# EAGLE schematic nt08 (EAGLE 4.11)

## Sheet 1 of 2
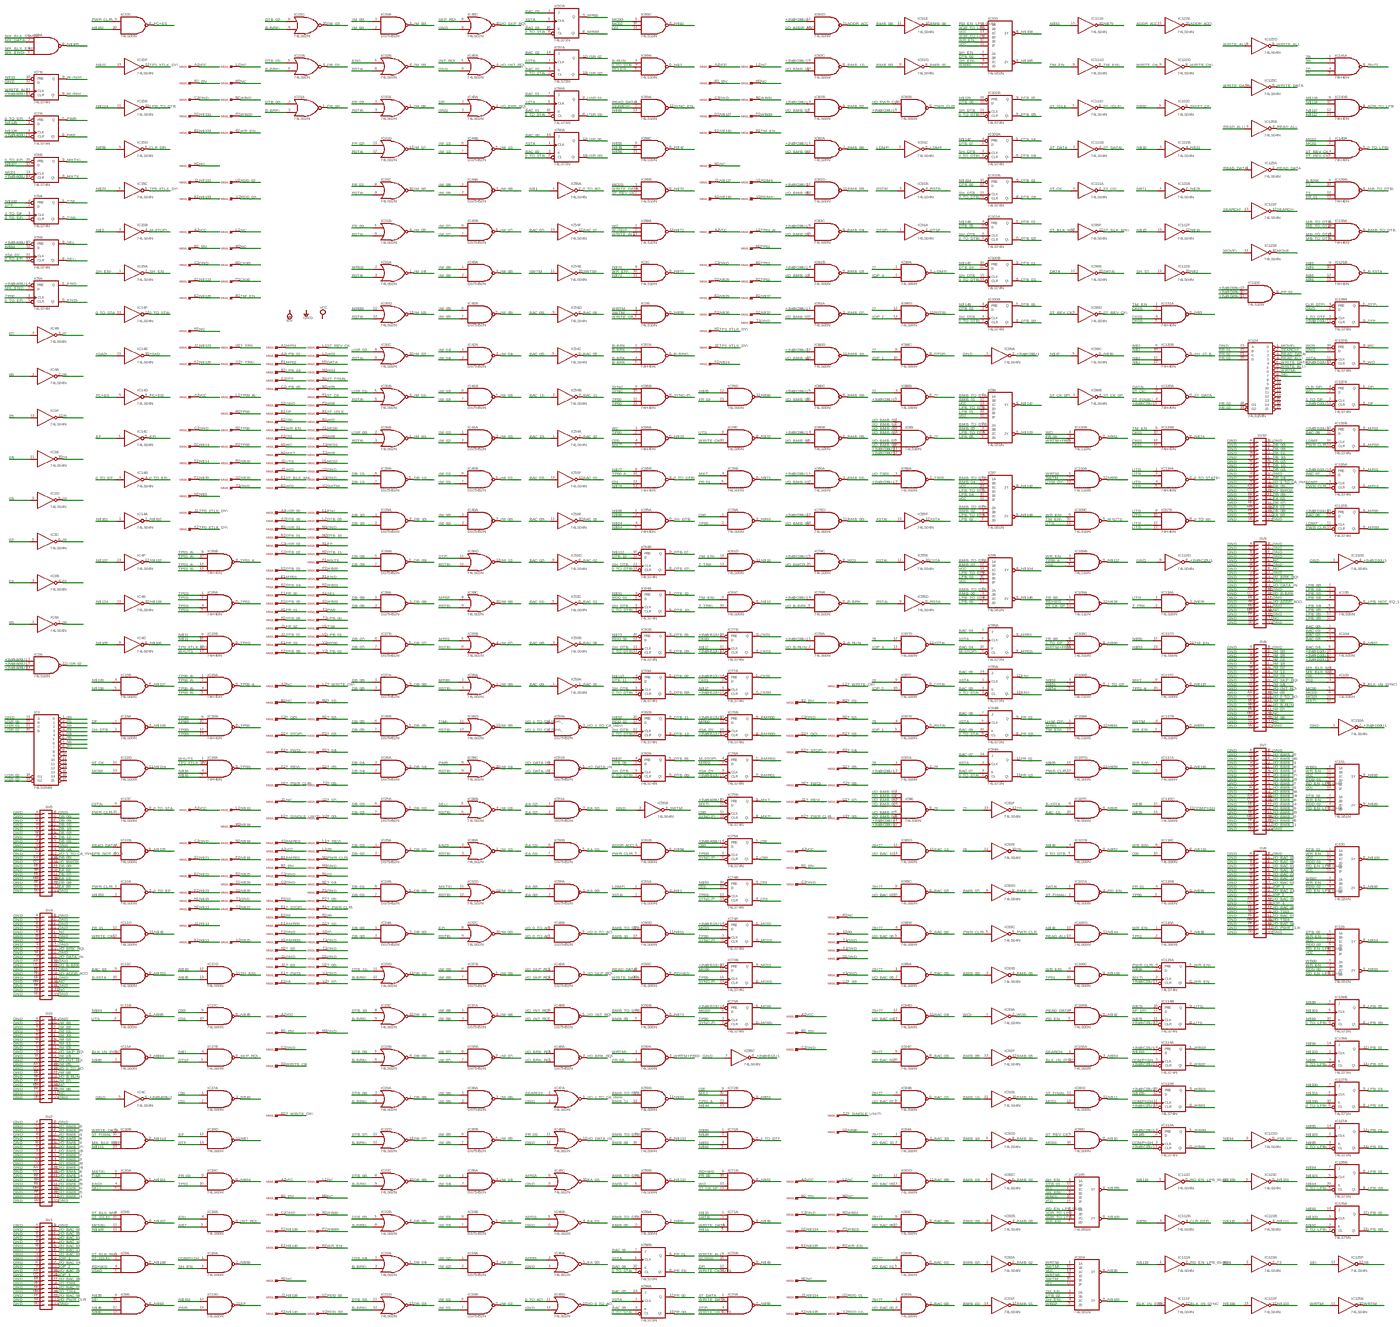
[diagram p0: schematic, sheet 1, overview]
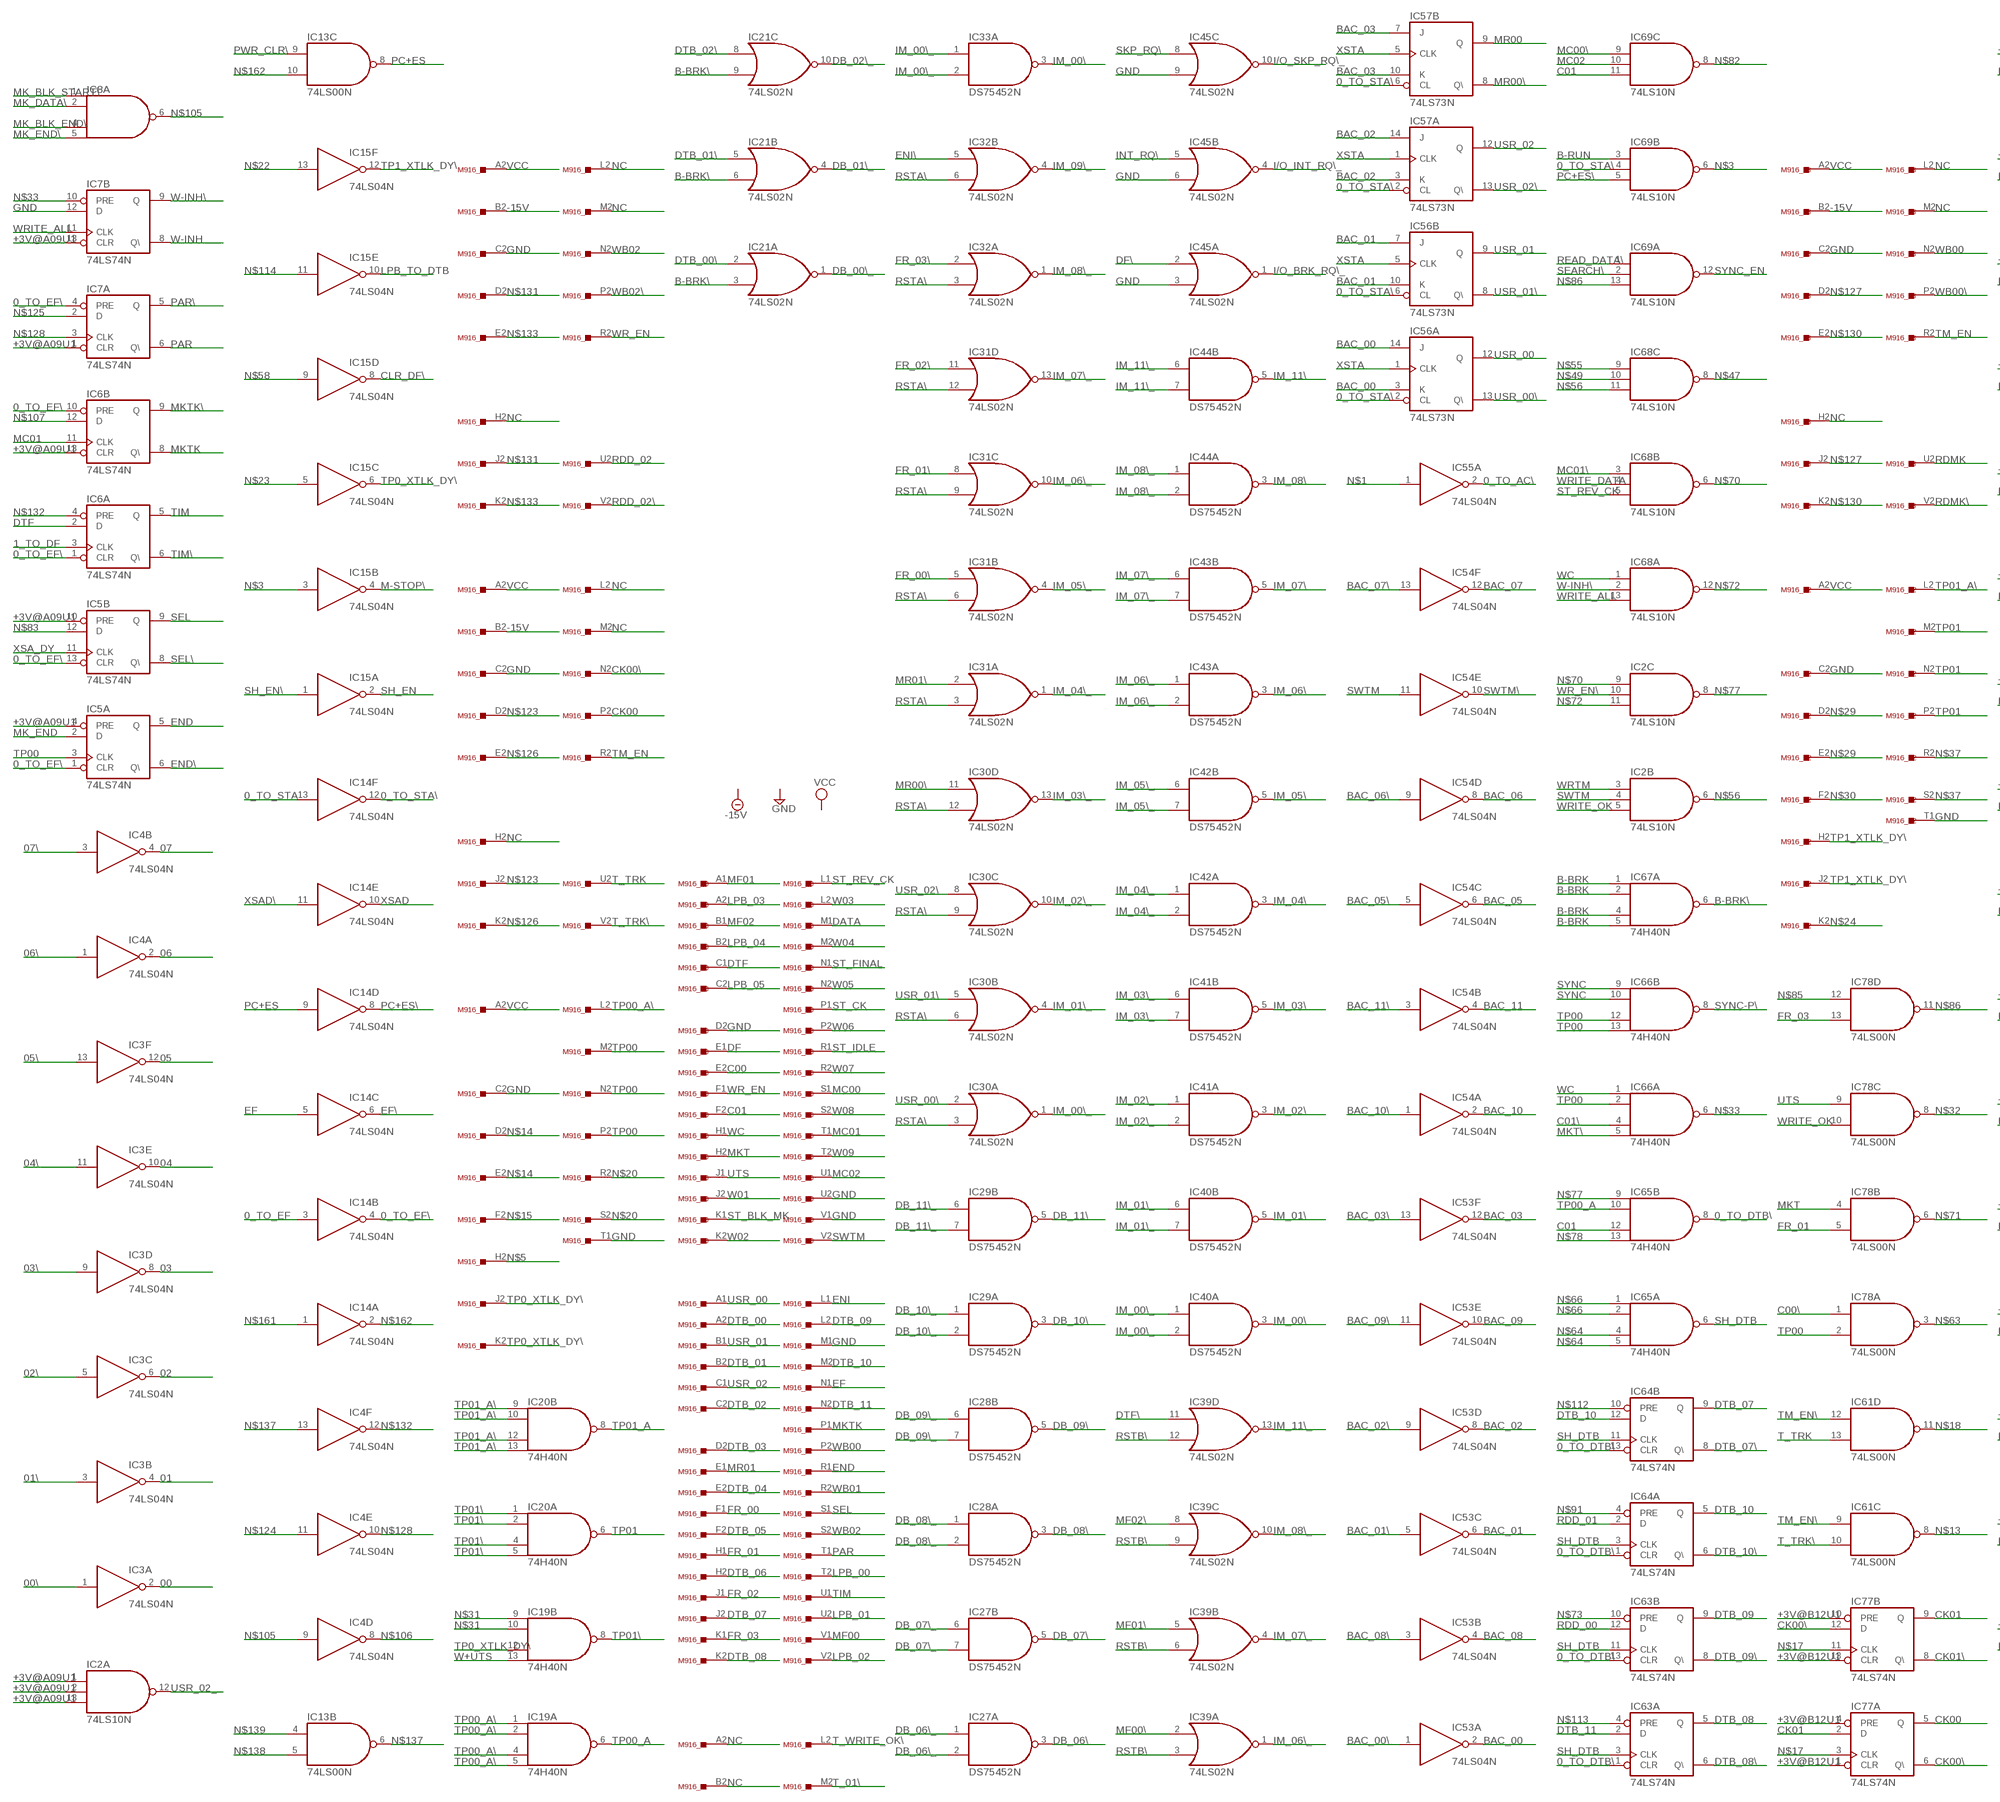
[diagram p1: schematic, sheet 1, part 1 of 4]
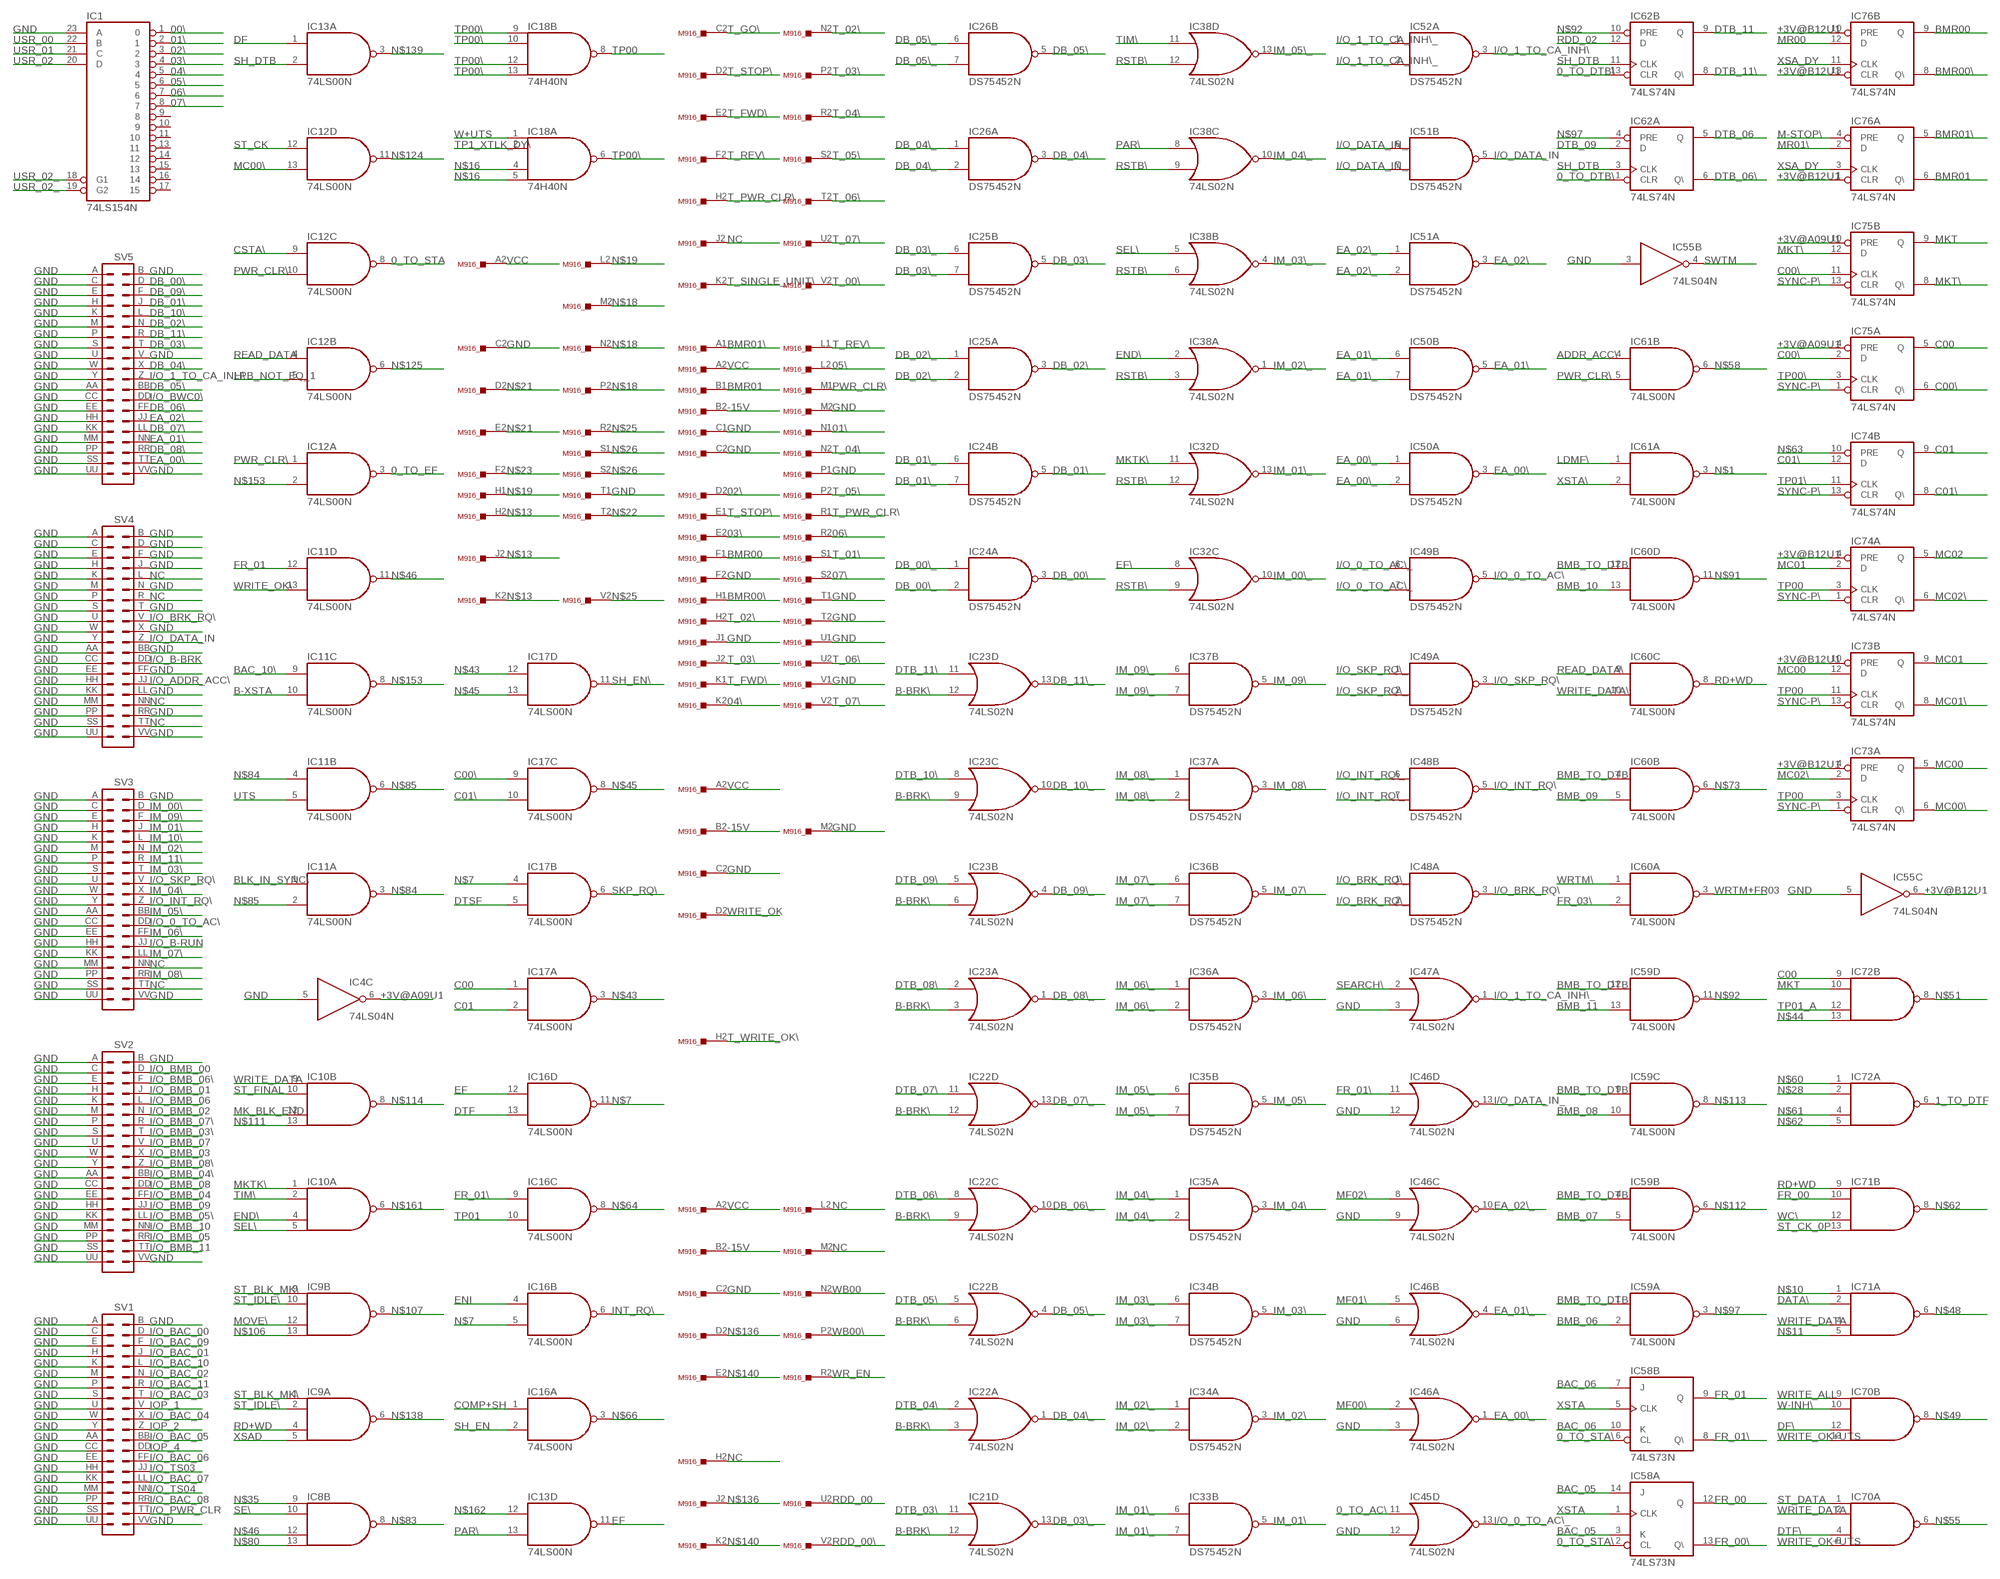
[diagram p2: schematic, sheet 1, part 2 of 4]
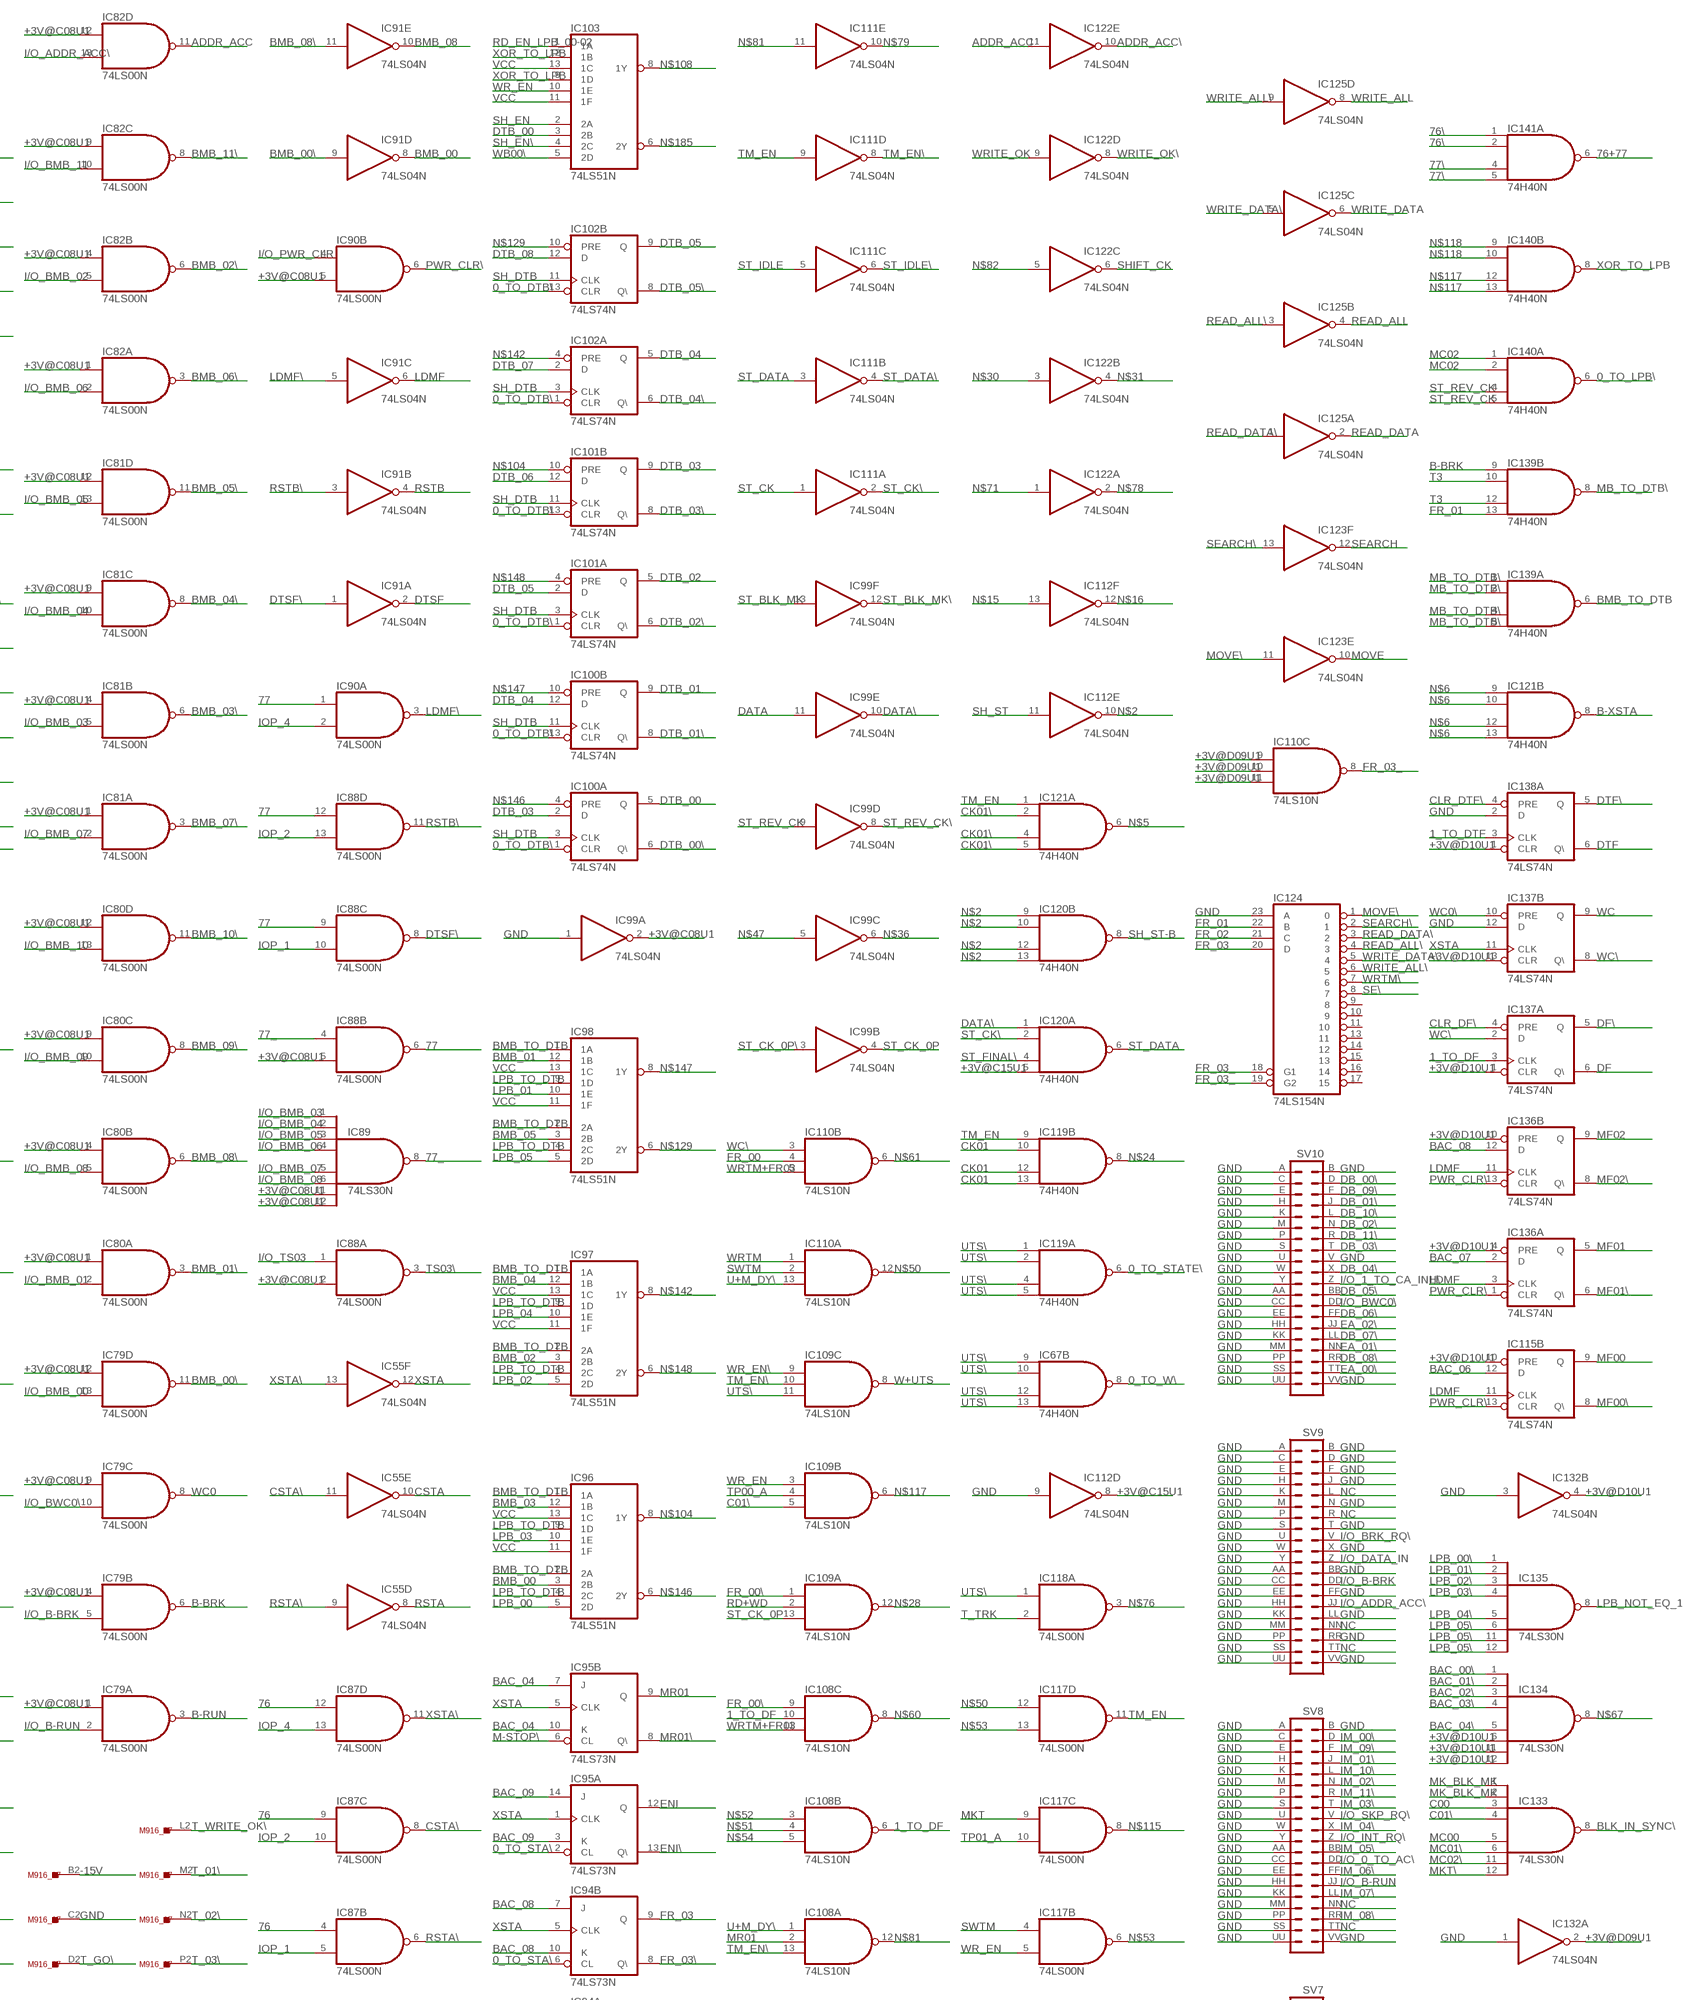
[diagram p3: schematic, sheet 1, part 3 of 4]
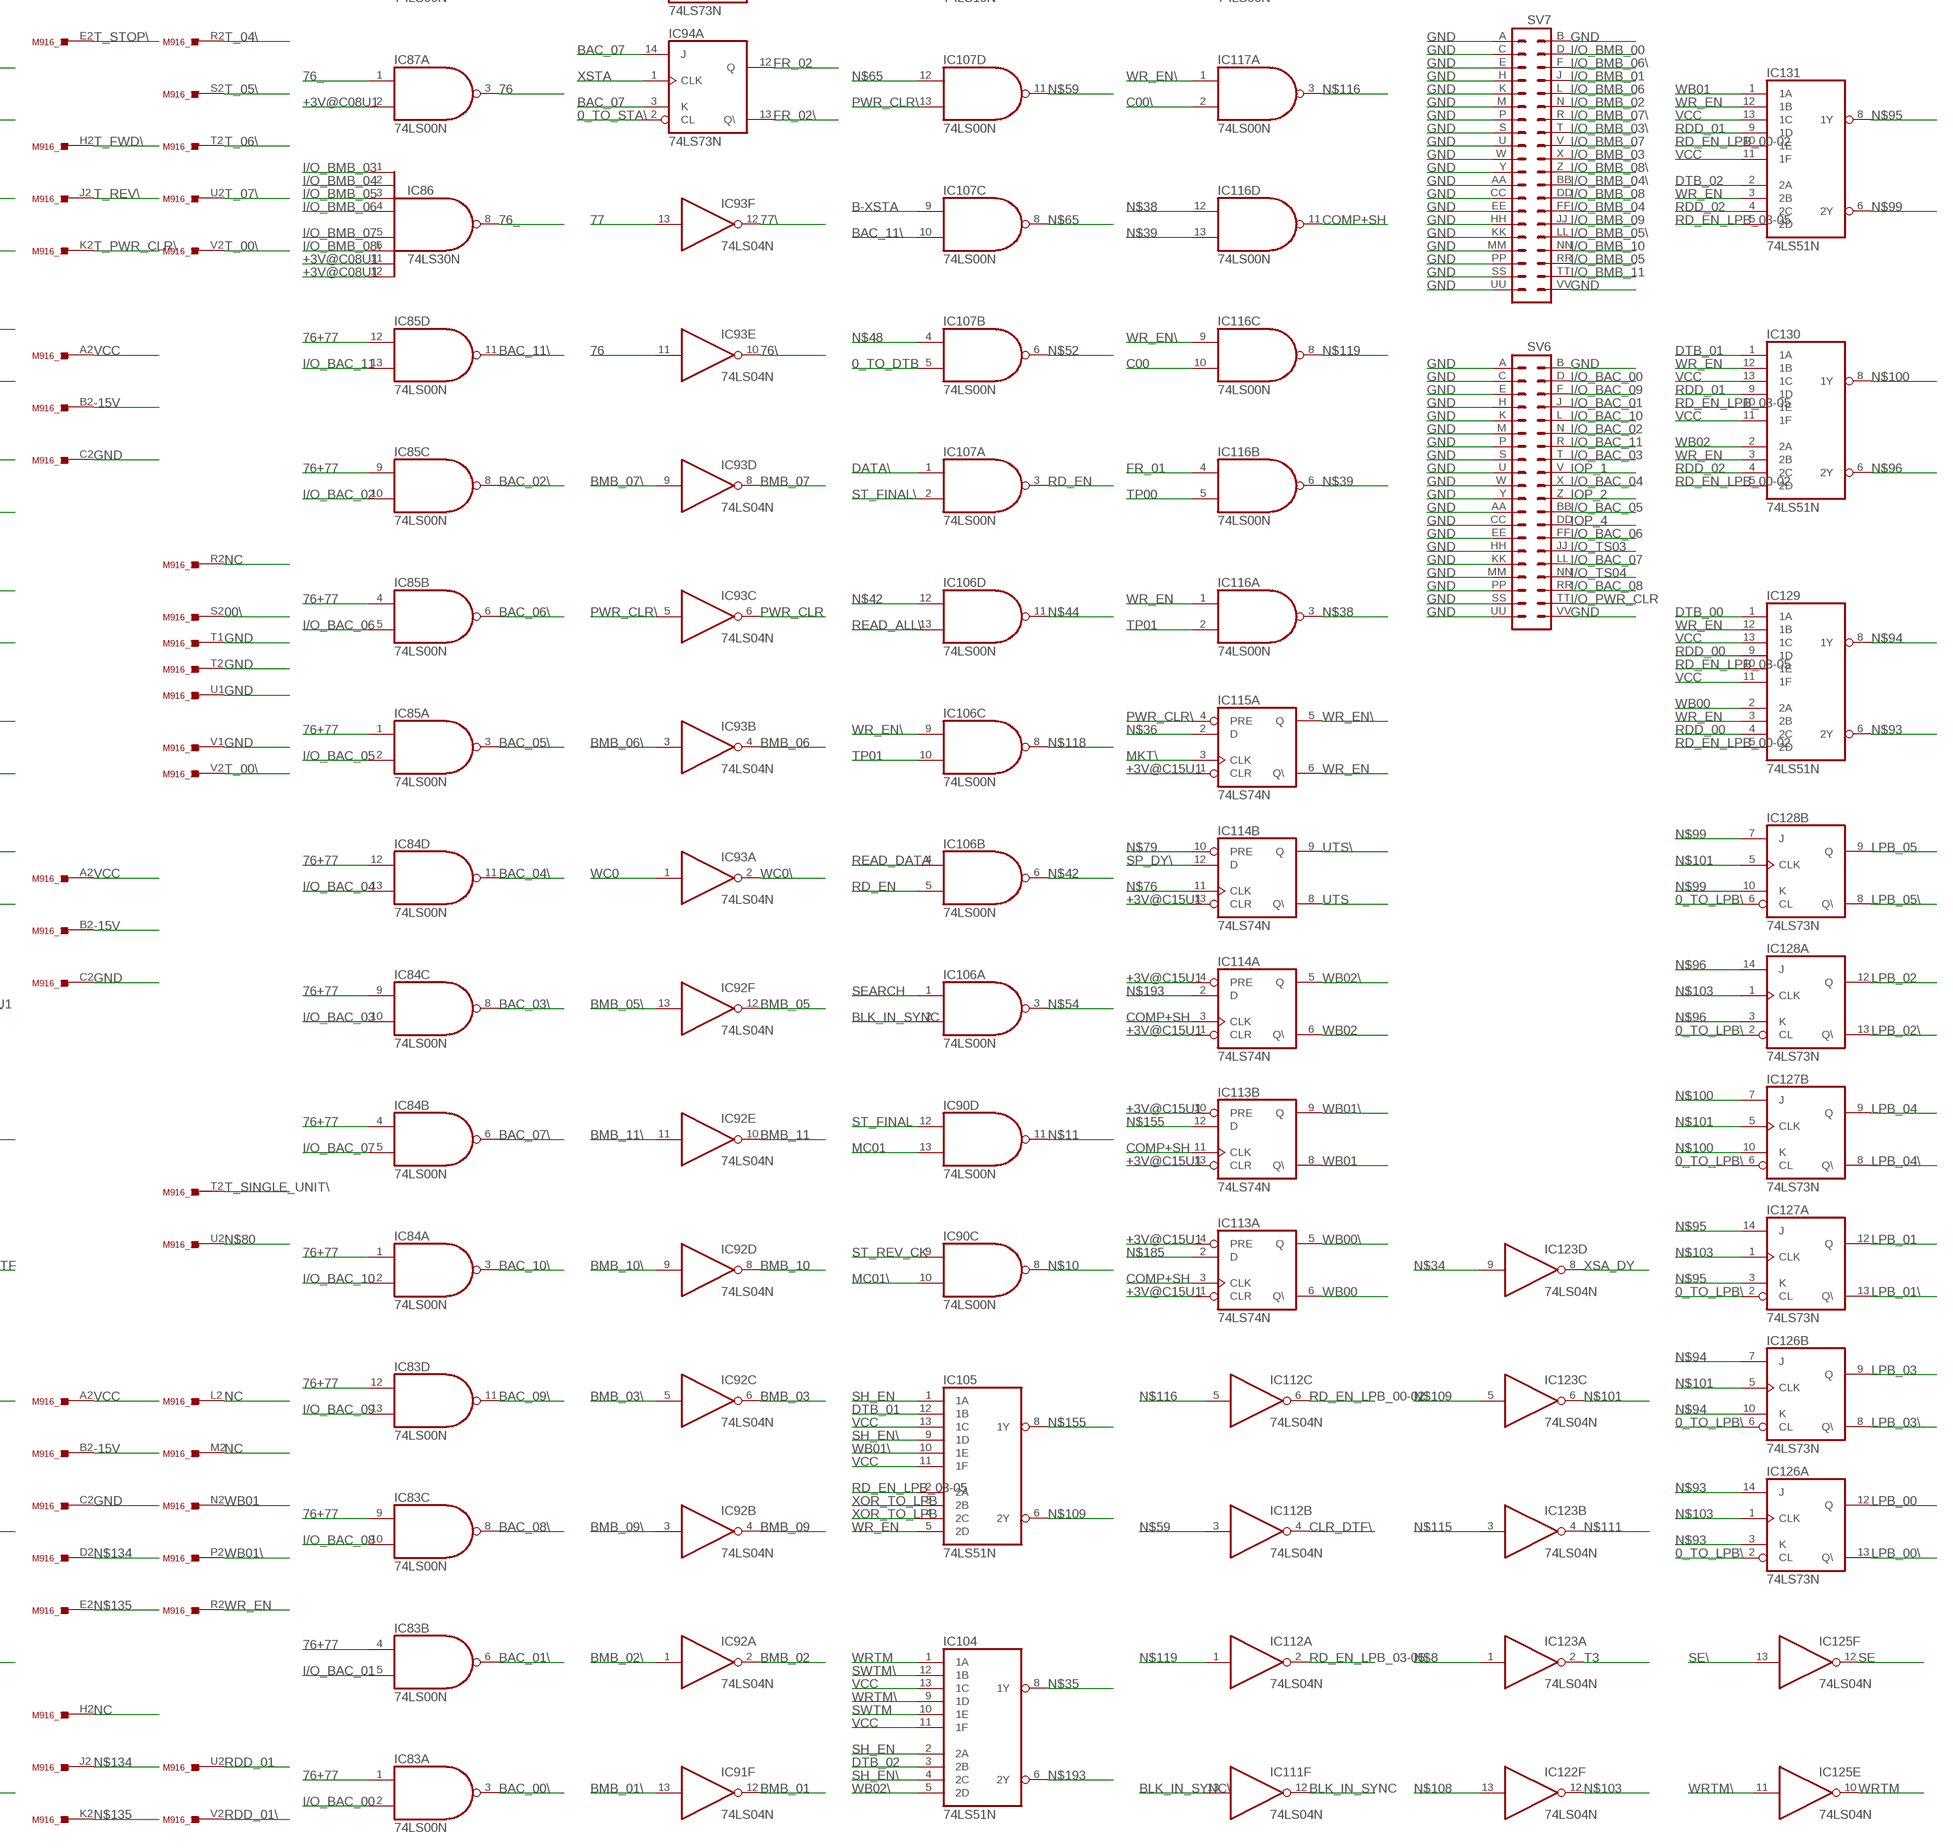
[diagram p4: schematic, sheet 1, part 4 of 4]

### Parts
IC1  74LS154N  [DIL24-6]
IC2  74LS10N  [DIL14]
IC3  74LS04N  [DIL14]
IC4  74LS04N  [DIL14]
IC5  74LS74N  [DIL14]
IC6  74LS74N  [DIL14]
IC7  74LS74N  [DIL14]
IC8  74LS20N  [DIL14]
IC9  74LS20N  [DIL14]
IC10  74LS20N  [DIL14]
IC11  74LS00N  [DIL14]
IC12  74LS00N  [DIL14]
IC13  74LS00N  [DIL14]
IC14  74LS04N  [DIL14]
IC15  74LS04N  [DIL14]
IC16  74LS00N  [DIL14]
IC17  74LS00N  [DIL14]
IC18  74H40N  74S20N  [DIL14]
IC19  74H40N  74S20N  [DIL14]
IC20  74H40N  74S20N  [DIL14]
IC21  74LS02N  [DIL14]
IC22  74LS02N  [DIL14]
IC23  74LS02N  [DIL14]
IC24  DS75452N  [DIL08]
IC25  DS75452N  [DIL08]
IC26  DS75452N  [DIL08]
IC27  DS75452N  [DIL08]
IC28  DS75452N  [DIL08]
IC29  DS75452N  [DIL08]
IC30  74LS02N  [DIL14]
IC31  74LS02N  [DIL14]
IC32  74LS02N  [DIL14]
IC33  DS75452N  [DIL08]
IC34  DS75452N  [DIL08]
IC35  DS75452N  [DIL08]
IC36  DS75452N  [DIL08]
IC37  DS75452N  [DIL08]
IC38  74LS02N  [DIL14]
IC39  74LS02N  [DIL14]
IC40  DS75452N  [DIL08]
IC41  DS75452N  [DIL08]
IC42  DS75452N  [DIL08]
IC43  DS75452N  [DIL08]
IC44  DS75452N  [DIL08]
IC45  74LS02N  [DIL14]
IC46  74LS02N  [DIL14]
IC47  74LS02N  [DIL14]
IC48  DS75452N  [DIL08]
IC49  DS75452N  [DIL08]
IC50  DS75452N  [DIL08]
IC51  DS75452N  [DIL08]
IC52  DS75452N  [DIL08]
IC53  74LS04N  [DIL14]
IC54  74LS04N  [DIL14]
IC55  74LS04N  [DIL14]
IC56  74LS73N  [DIL14]
IC57  74LS73N  [DIL14]
IC58  74LS73N  [DIL14]
IC59  74LS00N  [DIL14]
IC60  74LS00N  [DIL14]
IC61  74LS00N  [DIL14]
IC62  74LS74N  [DIL14]
IC63  74LS74N  [DIL14]
IC64  74LS74N  [DIL14]
IC65  74H40N  74S20N  [DIL14]
IC66  74H40N  74S20N  [DIL14]
IC67  74H40N  74S20N  [DIL14]
IC68  74LS10N  [DIL14]
IC69  74LS10N  [DIL14]
IC70  74LS20N  [DIL14]
IC71  74LS20N  [DIL14]
IC72  74LS20N  [DIL14]
IC73  74LS74N  [DIL14]
IC74  74LS74N  [DIL14]
IC75  74LS74N  [DIL14]
IC76  74LS74N  [DIL14]
IC77  74LS74N  [DIL14]
IC78  74LS00N  [DIL14]
IC79  74LS00N  [DIL14]
IC80  74LS00N  [DIL14]
IC81  74LS00N  [DIL14]
IC82  74LS00N  [DIL14]
IC83  74LS00N  [DIL14]
IC84  74LS00N  [DIL14]
IC85  74LS00N  [DIL14]
IC86  74LS30N  [DIL14]
IC87  74LS00N  [DIL14]
IC88  74LS00N  [DIL14]
IC89  74LS30N  [DIL14]
IC90  74LS00N  [DIL14]
IC91  74LS04N  [DIL14]
IC92  74LS04N  [DIL14]
IC93  74LS04N  [DIL14]
IC94  74LS73N  [DIL14]
IC95  74LS73N  [DIL14]
IC96  74LS51N  [DIL14]
IC97  74LS51N  [DIL14]
IC98  74LS51N  [DIL14]
IC99  74LS04N  [DIL14]
IC100  74LS74N  [DIL14]
IC101  74LS74N  [DIL14]
IC102  74LS74N  [DIL14]
IC103  74LS51N  [DIL14]
IC104  74LS51N  [DIL14]
IC105  74LS51N  [DIL14]
IC106  74LS00N  [DIL14]
IC107  74LS00N  [DIL14]
IC108  74LS10N  [DIL14]
IC109  74LS10N  [DIL14]
IC110  74LS10N  [DIL14]
IC111  74LS04N  [DIL14]
IC112  74LS04N  [DIL14]
IC113  74LS74N  [DIL14]
IC114  74LS74N  [DIL14]
IC115  74LS74N  [DIL14]
IC116  74LS00N  [DIL14]
IC117  74LS00N  [DIL14]
IC118  74LS00N  [DIL14]
IC119  74H40N  74S20N  [DIL14]
IC120  74H40N  74S20N  [DIL14]
IC121  74H40N  74S20N  [DIL14]
IC122  74LS04N  [DIL14]
IC123  74LS04N  [DIL14]
IC124  74LS154N  [DIL24-6]
IC125  74LS04N  [DIL14]
IC126  74LS73N  [DIL14]
IC127  74LS73N  [DIL14]
IC128  74LS73N  [DIL14]
IC129  74LS51N  [DIL14]
IC130  74LS51N  [DIL14]
IC131  74LS51N  [DIL14]
IC132  74LS04N  [DIL14]
IC133  74LS30N  [DIL14]
IC134  74LS30N  [DIL14]
IC135  74LS30N  [DIL14]
IC136  74LS74N  [DIL14]
IC137  74LS74N  [DIL14]
IC138  74LS74N  [DIL14]
IC139  74H40N  74S20N  [DIL14]
IC140  74H40N  74S20N  [DIL14]
IC141  74H40N  74S20N  [DIL14]
M916_1  M302  M916  [H807]
M916_2  M602  M916  [H807]
M916_3  G888  M916  [H807]
M916_4  M302  M916  [H807]
M916_5  G888  M916  [H807]
M916_6  G888  M916  [H807]
M916_7  M633  M916  [H807]
M916_8  W023  M916  [H807]
M916_9  M916  [H807]
M916_10  M916  [H807]
M916_12  M602  M916  [H807]
M916_13  G888  M916  [H807]
M916_14  G888  M916  [H807]
M916_15  G879  M916  [H807]
M916_16  M633  M916  [H807]
M916_17  W005  M916  [H807]
SV1  DEC40PIN  [DEC40PIN]
SV2  DEC40PIN  [DEC40PIN]
SV3  DEC40PIN  [DEC40PIN]
SV4  DEC40PIN  [DEC40PIN]
SV5  DEC40PIN  [DEC40PIN]
SV6  DEC40PIN  [DEC40PIN]
SV7  DEC40PIN  [DEC40PIN]
SV8  DEC40PIN  [DEC40PIN]
SV9  DEC40PIN  [DEC40PIN]
SV10  DEC40PIN  [DEC40PIN]

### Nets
00: IC3.2(A:O)
00\: IC1.1 IC3.1(A:I) M916_16.S2
0_TO_AC\: IC45.11(D:I0) IC55.2(A:O)
0_TO_DTB: IC107.5(B:I1)
0_TO_DTB\: IC62.1(A:CLR) IC62.13(B:CLR) IC63.1(A:CLR) IC63.13(B:CLR) IC64.1(A:CLR) IC64.13(B:CLR) IC65.8(B:O) IC100.1(A:CLR) IC100.13(B:CLR) IC101.1(A:CLR) IC101.13(B:CLR) IC102.1(A:CLR) IC102.13(B:CLR)
0_TO_EF: IC12.3(A:O) IC14.3(B:I)
0_TO_EF\: IC5.1(A:CLR) IC5.13(B:CLR) IC6.1(A:CLR) IC6.10(B:PRE) IC7.4(A:PRE) IC14.4(B:O)
0_TO_LPB\: IC126.2(A:CL) IC126.6(B:CL) IC127.2(A:CL) IC127.6(B:CL) IC128.2(A:CL) IC128.6(B:CL) IC140.6(A:O)
0_TO_STA: IC12.8(C:O) IC14.13(F:I)
0_TO_STA\: IC14.12(F:O) IC56.2(A:CL) IC56.6(B:CL) IC57.2(A:CL) IC57.6(B:CL) IC58.2(A:CL) IC58.6(B:CL) IC69.4(B:I1) IC94.2(A:CL) IC94.6(B:CL) IC95.2(A:CL)
0_TO_STATE\: IC119.6(A:O)
0_TO_W\: IC67.8(B:O)
01: IC3.4(B:O)
01\: IC1.2 IC3.3(B:I) M916_7.N1
1_TO_DF: IC6.3(A:CLK) IC108.6(B:O) IC108.10(C:I1) IC137.3(A:CLK)
1_TO_DTF: IC72.6(A:O) IC138.3(A:CLK)
02: IC3.6(C:O)
02\: IC1.3 IC3.5(C:I) M916_7.D2
03: IC3.8(D:O)
03\: IC1.4 IC3.9(D:I) M916_7.E2
04: IC3.10(E:O)
04\: IC1.5 IC3.11(E:I) M916_7.K2
05: IC3.12(F:O)
05\: IC1.6 IC3.13(F:I) M916_7.L2
06: IC4.2(A:O)
06\: IC1.7 IC4.1(A:I) M916_7.R2
07: IC4.4(B:O)
07\: IC1.8 IC4.3(B:I) M916_7.S2
76: IC87.3(A:O) IC87.4(B:I0) IC87.9(C:I0) IC87.12(D:I0) IC93.11(E:I)
76+77: IC83.1(A:I0) IC83.4(B:I0) IC83.9(C:I0) IC83.12(D:I0) IC84.1(A:I0) IC84.4(B:I0) IC84.9(C:I0) IC84.12(D:I0) IC85.1(A:I0) IC85.4(B:I0) IC85.9(C:I0) IC85.12(D:I0) IC141.6(A:O)
76\: IC93.10(E:O) IC141.1(A:I0) IC141.2(A:I1)
76_: IC86.8(O) IC87.1(A:I0)
77: IC88.6(B:O) IC88.9(C:I0) IC88.12(D:I0) IC90.1(A:I0) IC93.13(F:I)
77\: IC93.12(F:O) IC141.4(A:I2) IC141.5(A:I3)
77_: IC88.4(B:I0) IC89.8(O)
+3V@A09U1: IC2.1(A:I0) IC2.2(A:I1) IC2.13(A:I2) IC4.6(C:O) IC5.4(A:PRE) IC5.10(B:PRE) IC6.13(B:CLR) IC7.1(A:CLR) IC7.13(B:CLR) IC75.4(A:PRE) IC75.10(B:PRE)
+3V@B12U1: IC55.6(C:O) IC73.4(A:PRE) IC73.10(B:PRE) IC74.4(A:PRE) IC76.1(A:CLR) IC76.10(B:PRE) IC76.13(B:CLR) IC77.1(A:CLR) IC77.4(A:PRE) IC77.10(B:PRE) IC77.13(B:CLR)
+3V@C08U1: IC79.1(A:I0) IC79.4(B:I0) IC79.9(C:I0) IC79.12(D:I0) IC80.1(A:I0) IC80.4(B:I0) IC80.9(C:I0) IC80.12(D:I0) IC81.1(A:I0) IC81.4(B:I0) IC81.9(C:I0) IC81.12(D:I0) IC82.1(A:I0) IC82.4(B:I0) IC82.9(C:I0) IC82.12(D:I0) IC86.11(I6) IC86.12(I7) IC87.2(A:I1) IC88.2(A:I1) IC88.5(B:I1) IC89.11(I6) IC89.12(I7) IC90.5(B:I1) IC99.2(A:O)
+3V@C15U1: IC112.8(D:O) IC113.1(A:CLR) IC113.4(A:PRE) IC113.10(B:PRE) IC113.13(B:CLR) IC114.1(A:CLR) IC114.4(A:PRE) IC114.13(B:CLR) IC115.1(A:CLR) IC120.5(A:I3)
+3V@D09U1: IC110.9(C:I0) IC110.10(C:I1) IC110.11(C:I2) IC132.2(A:O)
+3V@D10U1: IC115.10(B:PRE) IC132.4(B:O) IC134.6(I5) IC134.11(I6) IC134.12(I7) IC136.4(A:PRE) IC136.10(B:PRE) IC137.1(A:CLR) IC137.13(B:CLR) IC138.1(A:CLR) ; also sheet 2
-15V: M916_3.B2 M916_4.B2 M916_5.B2 M916_6.B2 M916_7.B2 M916_13.B2 M916_14.B2 M916_15.B2 M916_16.B2 M916_17.B2
ADDR_ACC: IC82.11(D:O) IC122.11(E:I)
ADDR_ACC\: IC61.4(B:I0) IC122.10(E:O)
B-BRK: IC67.1(A:I0) IC67.2(A:I1) IC67.4(A:I2) IC67.5(A:I3) IC79.6(B:O) IC139.9(B:I0)
B-BRK\: IC21.3(A:I1) IC21.6(B:I1) IC21.9(C:I1) IC21.12(D:I1) IC22.3(A:I1) IC22.6(B:I1) IC22.9(C:I1) IC22.12(D:I1) IC23.3(A:I1) IC23.6(B:I1) IC23.9(C:I1) IC23.12(D:I1) IC67.6(A:O)
B-RUN: IC69.3(B:I0) IC79.3(A:O)
B-XSTA: IC11.10(C:I1) IC107.9(C:I0) IC121.8(B:O)
BAC_00: IC53.2(A:O) IC56.3(A:K) IC56.14(A:J)
BAC_00\: IC53.1(A:I) IC83.3(A:O) IC134.1(I0)
BAC_01: IC53.6(C:O) IC56.7(B:J) IC56.10(B:K)
BAC_01\: IC53.5(C:I) IC83.6(B:O) IC134.2(I1)
BAC_02: IC53.8(D:O) IC57.3(A:K) IC57.14(A:J)
BAC_02\: IC53.9(D:I) IC85.8(C:O) IC134.3(I2)
BAC_03: IC53.12(F:O) IC57.7(B:J) IC57.10(B:K)
BAC_03\: IC53.13(F:I) IC84.8(C:O) IC134.4(I3)
BAC_04: IC95.7(B:J) IC95.10(B:K)
BAC_04\: IC84.11(D:O) IC134.5(I4)
BAC_05: IC54.6(C:O) IC58.3(A:K) IC58.14(A:J)
BAC_05\: IC54.5(C:I) IC85.3(A:O)
BAC_06: IC54.8(D:O) IC58.7(B:J) IC58.10(B:K) IC115.12(B:D)
BAC_06\: IC54.9(D:I) IC85.6(B:O)
BAC_07: IC54.12(F:O) IC94.3(A:K) IC94.14(A:J) IC136.2(A:D)
BAC_07\: IC54.13(F:I) IC84.6(B:O)
BAC_08: IC53.4(B:O) IC94.7(B:J) IC94.10(B:K) IC136.12(B:D)
BAC_08\: IC53.3(B:I) IC83.8(C:O)
BAC_09: IC53.10(E:O) IC95.3(A:K) IC95.14(A:J)
BAC_09\: IC53.11(E:I) IC83.11(D:O)
BAC_10: IC54.2(A:O)
BAC_10\: IC11.9(C:I0) IC54.1(A:I) IC84.3(A:O)
BAC_11: IC54.4(B:O)
BAC_11\: IC54.3(B:I) IC85.11(D:O) IC107.10(C:I1)
BLK_IN_SYNC: IC106.2(A:I1) IC111.12(F:O)
BLK_IN_SYNC\: IC11.1(A:I0) IC111.13(F:I) IC133.8(O)
BMB_00: IC91.8(D:O) IC96.3(2B)
BMB_00\: IC79.11(D:O) IC91.9(D:I)
BMB_01: IC91.12(F:O) IC98.12(1B)
BMB_01\: IC80.3(A:O) IC91.13(F:I)
BMB_02: IC92.2(A:O) IC97.3(2B)
BMB_02\: IC82.6(B:O) IC92.1(A:I)
BMB_03: IC92.6(C:O) IC96.12(1B)
BMB_03\: IC81.6(B:O) IC92.5(C:I)
BMB_04: IC97.12(1B)
BMB_04\: IC81.8(C:O)
BMB_05: IC92.12(F:O) IC98.3(2B)
BMB_05\: IC81.11(D:O) IC92.13(F:I)
BMB_06: IC59.2(A:I1) IC93.4(B:O)
BMB_06\: IC82.3(A:O) IC93.3(B:I)
BMB_07: IC59.5(B:I1) IC93.8(D:O)
BMB_07\: IC81.3(A:O) IC93.9(D:I)
BMB_08: IC59.10(C:I1) IC91.10(E:O)
BMB_08\: IC80.6(B:O) IC91.11(E:I)
BMB_09: IC60.5(B:I1) IC92.4(B:O)
BMB_09\: IC80.8(C:O) IC92.3(B:I)
BMB_10: IC60.13(D:I1) IC92.8(D:O)
BMB_10\: IC80.11(D:O) IC92.9(D:I)
BMB_11: IC59.13(D:I1) IC92.10(E:O)
BMB_11\: IC82.8(C:O) IC92.11(E:I)
BMB_TO_DTB: IC59.1(A:I0) IC59.4(B:I0) IC59.9(C:I0) IC59.12(D:I0) IC60.4(B:I0) IC60.12(D:I0) IC96.1(1A) IC96.2(2A) IC97.1(1A) IC97.2(2A) IC98.1(1A) IC98.2(2A) IC139.6(A:O)
BMR00: IC76.9(B:Q) M916_7.F1
BMR00\: IC76.8(B:Q\) M916_7.H1
BMR01: IC76.6(A:Q\) M916_7.B1
BMR01\: IC76.5(A:Q) M916_7.A1
C00: IC17.1(A:I0) IC72.9(B:I0) IC75.5(A:Q) IC116.10(C:I1) IC133.3(I2) M916_10.E2
C00\: IC17.9(C:I0) IC75.2(A:D) IC75.6(A:Q\) IC75.11(B:CLK) IC78.1(A:I0) IC117.2(A:I1)
C01: IC17.2(A:I1) IC65.12(B:I2) IC69.11(C:I2) IC74.9(B:Q) M916_10.F2
C01\: IC17.10(C:I1) IC66.4(A:I2) IC74.8(B:Q\) IC74.12(B:D) IC109.5(B:I2) IC133.4(I3)
CK00: IC77.5(A:Q) M916_3.P2
CK00\: IC77.6(A:Q\) IC77.12(B:D) M916_3.N2
CK01: IC77.2(A:D) IC77.9(B:Q) IC119.10(B:I1) IC119.12(B:I2) IC119.13(B:I3)
CK01\: IC77.8(B:Q\) IC121.2(A:I1) IC121.4(A:I2) IC121.5(A:I3)
CLR_DF\: IC15.8(D:O) IC137.4(A:PRE)
CLR_DTF\: IC112.4(B:O) IC138.4(A:PRE)
COMP+SH: IC16.1(A:I0) IC113.3(A:CLK) IC113.11(B:CLK) IC114.3(A:CLK) IC116.11(D:O)
CSTA: IC55.10(E:O) ; also sheet 2
CSTA\: IC12.9(C:I0) IC55.11(E:I) IC87.8(C:O)
DATA: IC99.11(E:I) M916_10.M1
DATA\: IC71.2(A:I1) IC99.10(E:O) IC107.1(A:I0) IC120.1(A:I0)
DB_00\: IC24.3(A:O) SV5.D SV10.D
DB_00\_: IC21.1(A:O) IC24.1(A:I0) IC24.2(A:I1)
DB_01\: IC24.5(B:O) SV5.J SV10.J
DB_01\_: IC21.4(B:O) IC24.6(B:I0) IC24.7(B:I1)
DB_02\: IC25.3(A:O) SV5.N SV10.N
DB_02\_: IC21.10(C:O) IC25.1(A:I0) IC25.2(A:I1)
DB_03\: IC25.5(B:O) SV5.T SV10.T
DB_03\_: IC21.13(D:O) IC25.6(B:I0) IC25.7(B:I1)
DB_04\: IC26.3(A:O) SV5.X SV10.X
DB_04\_: IC22.1(A:O) IC26.1(A:I0) IC26.2(A:I1)
DB_05\: IC26.5(B:O) SV5.BB SV10.BB
DB_05\_: IC22.4(B:O) IC26.6(B:I0) IC26.7(B:I1)
DB_06\: IC27.3(A:O) SV5.FF SV10.FF
DB_06\_: IC22.10(C:O) IC27.1(A:I0) IC27.2(A:I1)
DB_07\: IC27.5(B:O) SV5.LL SV10.LL
DB_07\_: IC22.13(D:O) IC27.6(B:I0) IC27.7(B:I1)
DB_08\: IC28.3(A:O) SV5.RR SV10.RR
DB_08\_: IC23.1(A:O) IC28.1(A:I0) IC28.2(A:I1)
DB_09\: IC28.5(B:O) SV5.F SV10.F
DB_09\_: IC23.4(B:O) IC28.6(B:I0) IC28.7(B:I1)
DB_10\: IC29.3(A:O) SV5.L SV10.L
DB_10\_: IC23.10(C:O) IC29.1(A:I0) IC29.2(A:I1)
DB_11\: IC29.5(B:O) SV5.R SV10.R
DB_11\_: IC23.13(D:O) IC29.6(B:I0) IC29.7(B:I1)
DF: IC13.1(A:I0) IC137.6(A:Q\) M916_10.E1
DF\: IC45.2(A:I0) IC70.12(B:I2) IC137.5(A:Q)
DTB_00: IC100.5(A:Q) IC103.3(2B) IC129.1(1A) M916_9.A2
DTB_00\: IC21.2(A:I0) IC100.6(A:Q\)
DTB_01: IC100.9(B:Q) IC105.12(1B) IC130.1(1A) M916_9.B2
DTB_01\: IC21.5(B:I0) IC100.8(B:Q\)
DTB_02: IC101.5(A:Q) IC104.3(2B) IC131.2(2A) M916_9.C2
DTB_02\: IC21.8(C:I0) IC101.6(A:Q\)
DTB_03: IC100.2(A:D) IC101.9(B:Q) M916_9.D2
DTB_03\: IC21.11(D:I0) IC101.8(B:Q\)
DTB_04: IC100.12(B:D) IC102.5(A:Q) M916_9.E2
DTB_04\: IC22.2(A:I0) IC102.6(A:Q\)
DTB_05: IC101.2(A:D) IC102.9(B:Q) M916_9.F2
DTB_05\: IC22.5(B:I0) IC102.8(B:Q\)
DTB_06: IC62.5(A:Q) IC101.12(B:D) M916_9.H2
DTB_06\: IC22.8(C:I0) IC62.6(A:Q\)
DTB_07: IC64.9(B:Q) IC102.2(A:D) M916_9.J2
DTB_07\: IC22.11(D:I0) IC64.8(B:Q\)
DTB_08: IC63.5(A:Q) IC102.12(B:D) M916_9.K2
DTB_08\: IC23.2(A:I0) IC63.6(A:Q\)
DTB_09: IC62.2(A:D) IC63.9(B:Q) M916_9.L2
DTB_09\: IC23.5(B:I0) IC63.8(B:Q\)
DTB_10: IC64.5(A:Q) IC64.12(B:D) M916_9.M2
DTB_10\: IC23.8(C:I0) IC64.6(A:Q\)
DTB_11: IC62.9(B:Q) IC63.2(A:D) M916_9.N2
DTB_11\: IC23.11(D:I0) IC62.8(B:Q\)
DTF: IC6.2(A:D) IC16.13(D:I1) IC138.6(A:Q\) M916_10.C1
DTF\: IC39.11(D:I0) IC70.4(A:I2) IC138.5(A:Q)
DTSF: IC17.5(B:I1) IC91.2(A:O)
DTSF\: IC88.8(C:O) IC91.1(A:I)
EA_00\: IC50.3(A:O) SV5.TT SV10.TT
EA_00\_: IC46.1(A:O) IC50.1(A:I0) IC50.2(A:I1)
EA_01\: IC50.5(B:O) SV5.NN SV10.NN
EA_01\_: IC46.4(B:O) IC50.6(B:I0) IC50.7(B:I1)
EA_02\: IC51.3(A:O) SV5.JJ SV10.JJ
EA_02\_: IC46.10(C:O) IC51.1(A:I0) IC51.2(A:I1)
EF: IC13.11(D:O) IC14.5(C:I) IC16.12(D:I0) M916_9.N1
EF\: IC14.6(C:O) IC32.8(C:I0)
END: IC5.5(A:Q) M916_9.R1
END\: IC5.6(A:Q\) IC10.4(A:I2) IC38.2(A:I0)
ENI: IC16.4(B:I0) IC95.12(A:Q) M916_9.L1
ENI\: IC32.5(B:I0) IC95.13(A:Q\)
FR_00: IC58.12(A:Q) IC71.10(B:I1) IC110.4(B:I1) M916_9.F1
FR_00\: IC31.5(B:I0) IC58.13(A:Q\) IC108.9(C:I0) IC109.1(A:I0)
FR_01: IC11.12(D:I0) IC58.9(B:Q) IC78.5(B:I1) IC116.4(B:I0) IC124.22(B) IC139.13(B:I3) M916_9.H1
FR_01\: IC16.9(C:I0) IC31.8(C:I0) IC46.11(D:I0) IC58.8(B:Q\)
FR_02: IC94.12(A:Q) IC124.21(C) M916_9.J1
FR_02\: IC31.11(D:I0) IC94.13(A:Q\)
FR_03: IC78.13(D:I1) IC94.9(B:Q) IC124.20(D) M916_9.K1
FR_03\: IC32.2(A:I0) IC60.2(A:I1) IC94.8(B:Q\)
FR_03_: IC110.8(C:O) IC124.18(G1) IC124.19(G2)
GND: IC1.23(A) IC4.5(C:I) IC7.12(B:D) IC45.3(A:I1) IC45.6(B:I1) IC45.9(C:I1) IC45.12(D:I1) IC46.3(A:I1) IC46.6(B:I1) IC46.9(C:I1) IC46.12(D:I1) IC47.3(A:I1) IC55.3(B:I) IC55.5(C:I) IC99.1(A:I) IC112.9(D:I) IC124.23(A) IC132.1(A:I) IC132.3(B:I) IC137.12(B:D) IC138.2(A:D) M916_1.C2 M916_1.T1 M916_2.C2 M916_2.T1 M916_3.C2 M916_4.C2 M916_5.C2 M916_6.C2 M916_6.M2 M916_7.C1 M916_7.C2 M916_7.F2 M916_7.J1 M916_7.M2 M916_7.P1 M916_7.T1 M916_7.T2 M916_7.U1 M916_7.V1 M916_9.M1 M916_10.D2 M916_10.U2 M916_10.V1 M916_12.C2 M916_12.T1 M916_13.C2 M916_14.C2 M916_15.C2 M916_16.C2 M916_16.T1 M916_16.T2 M916_16.U1 M916_16.V1 M916_17.C2 SV1.A SV1.AA SV1.B SV1.C SV1.CC SV1.E SV1.EE SV1.H SV1.HH SV1.K SV1.KK SV1.M SV1.MM SV1.P SV1.PP SV1.S SV1.SS SV1.U SV1.UU SV1.VV SV1.W SV1.Y SV2.A SV2.AA SV2.B SV2.C SV2.CC SV2.E SV2.EE SV2.H SV2.HH SV2.K SV2.KK SV2.M SV2.MM SV2.P SV2.PP SV2.S SV2.SS SV2.U SV2.UU SV2.VV SV2.W SV2.Y SV3.A SV3.AA SV3.B SV3.C SV3.CC SV3.E SV3.EE SV3.H SV3.HH SV3.K SV3.KK SV3.M SV3.MM SV3.P SV3.PP SV3.S SV3.SS SV3.U SV3.UU SV3.VV SV3.W SV3.Y SV4.A SV4.AA SV4.B SV4.BB SV4.C SV4.CC SV4.D SV4.E SV4.EE SV4.F SV4.FF SV4.H SV4.HH SV4.J SV4.K SV4.KK SV4.LL SV4.M SV4.MM SV4.N SV4.P SV4.PP SV4.RR SV4.S SV4.SS SV4.T SV4.U SV4.UU SV4.VV SV4.W SV4.X SV4.Y SV5.A SV5.AA SV5.B SV5.C SV5.CC SV5.E SV5.EE SV5.H SV5.HH SV5.K SV5.KK SV5.M SV5.MM SV5.P SV5.PP SV5.S SV5.SS SV5.U SV5.UU SV5.V SV5.VV SV5.W SV5.Y SV6.A SV6.AA SV6.B SV6.C SV6.CC SV6.E SV6.EE SV6.H SV6.HH SV6.K SV6.KK SV6.M SV6.MM SV6.P SV6.PP SV6.S SV6.SS SV6.U SV6.UU SV6.VV SV6.W SV6.Y SV7.A SV7.AA SV7.B SV7.C SV7.CC SV7.E SV7.EE SV7.H SV7.HH SV7.K SV7.KK SV7.M SV7.MM SV7.P SV7.PP SV7.S SV7.SS SV7.U SV7.UU SV7.VV SV7.W SV7.Y SV8.A SV8.AA SV8.B SV8.C SV8.CC SV8.E SV8.EE SV8.H SV8.HH SV8.K SV8.KK SV8.M SV8.MM SV8.P SV8.PP SV8.S SV8.SS SV8.U SV8.UU SV8.VV SV8.W SV8.Y SV9.A SV9.AA SV9.B SV9.BB SV9.C SV9.CC SV9.D SV9.E SV9.EE SV9.F SV9.FF SV9.H SV9.HH SV9.J SV9.K SV9.KK SV9.LL SV9.M SV9.MM SV9.N SV9.P SV9.PP SV9.RR SV9.S SV9.SS SV9.T SV9.U SV9.UU SV9.VV SV9.W SV9.X SV9.Y SV10.A SV10.AA SV10.B SV10.C SV10.CC SV10.E SV10.EE SV10.H SV10.HH SV10.K SV10.KK SV10.M SV10.MM SV10.P SV10.PP SV10.S SV10.SS SV10.U SV10.UU SV10.V SV10.VV SV10.W SV10.Y ; also sheet 2
I/O_0_TO_AC\: IC49.5(B:O) SV3.DD SV8.DD
I/O_0_TO_AC\_: IC45.13(D:O) IC49.6(B:I0) IC49.7(B:I1)
I/O_1_TO_CA_INH\: IC52.3(A:O) SV5.Z SV10.Z
I/O_1_TO_CA_INH\_: IC47.1(A:O) IC52.1(A:I0) IC52.2(A:I1)
I/O_ADDR_ACC\: IC82.13(D:I1) SV4.JJ SV9.JJ
I/O_B-BRK: IC79.5(B:I1) SV4.DD SV9.DD
I/O_B-RUN: IC79.2(A:I1) SV3.JJ SV8.JJ
I/O_BAC_00: IC83.2(A:I1) SV1.D SV6.D
I/O_BAC_01: IC83.5(B:I1) SV1.J SV6.J
I/O_BAC_02: IC85.10(C:I1) SV1.N SV6.N
I/O_BAC_03: IC84.10(C:I1) SV1.T SV6.T
I/O_BAC_04: IC84.13(D:I1) SV1.X SV6.X
I/O_BAC_05: IC85.2(A:I1) SV1.BB SV6.BB
I/O_BAC_06: IC85.5(B:I1) SV1.FF SV6.FF
I/O_BAC_07: IC84.5(B:I1) SV1.LL SV6.LL
I/O_BAC_08: IC83.10(C:I1) SV1.RR SV6.RR
I/O_BAC_09: IC83.13(D:I1) SV1.F SV6.F
I/O_BAC_10: IC84.2(A:I1) SV1.L SV6.L
I/O_BAC_11: IC85.13(D:I1) SV1.R SV6.R
I/O_BMB_00: IC79.13(D:I1) SV2.D SV7.D
I/O_BMB_01: IC80.2(A:I1) SV2.J SV7.J
I/O_BMB_02: IC82.5(B:I1) SV2.N SV7.N
I/O_BMB_03: IC81.5(B:I1) IC86.1(I0) IC89.1(I0) SV2.X SV7.X
I/O_BMB_03\: SV2.T SV7.T
I/O_BMB_04: IC81.10(C:I1) IC86.2(I1) IC89.2(I1) SV2.FF SV7.FF
I/O_BMB_04\: SV2.BB SV7.BB
I/O_BMB_05: IC81.13(D:I1) IC86.3(I2) IC89.3(I2) SV2.RR SV7.RR
I/O_BMB_05\: SV2.LL SV7.LL
I/O_BMB_06: IC82.2(A:I1) IC86.4(I3) IC89.4(I3) SV2.L SV7.L
I/O_BMB_06\: SV2.F SV7.F
I/O_BMB_07: IC81.2(A:I1) IC86.5(I4) IC89.5(I4) SV2.V SV7.V
I/O_BMB_07\: SV2.R SV7.R
I/O_BMB_08: IC80.5(B:I1) IC89.6(I5) SV2.DD SV7.DD
I/O_BMB_08\: IC86.6(I5) SV2.Z SV7.Z
I/O_BMB_09: IC80.10(C:I1) SV2.JJ SV7.JJ
I/O_BMB_10: IC80.13(D:I1) SV2.NN SV7.NN
I/O_BMB_11: IC82.10(C:I1) SV2.TT SV7.TT
I/O_BRK_RQ\: IC48.3(A:O) SV4.V SV9.V
I/O_BRK_RQ\_: IC45.1(A:O) IC48.1(A:I0) IC48.2(A:I1)
I/O_BWC0\: IC79.10(C:I1) SV5.DD SV10.DD
I/O_DATA_IN: IC51.5(B:O) SV4.Z SV9.Z
I/O_DATA_IN_: IC46.13(D:O) IC51.6(B:I0) IC51.7(B:I1)
I/O_INT_RQ\: IC48.5(B:O) SV3.Z SV8.Z
I/O_INT_RQ\_: IC45.4(B:O) IC48.6(B:I0) IC48.7(B:I1)
I/O_PWR_CLR: IC90.4(B:I0) SV1.TT SV6.TT
I/O_SKP_RQ\: IC49.3(A:O) SV3.V SV8.V
I/O_SKP_RQ\_: IC45.10(C:O) IC49.1(A:I0) IC49.2(A:I1)
I/O_TS03: IC88.1(A:I0) SV1.JJ SV6.JJ
I/O_TS04: SV1.NN SV6.NN
IM_00\: IC33.3(A:O) IC40.3(A:O) SV3.D SV8.D
IM_00\_: IC30.1(A:O) IC32.10(C:O) IC33.1(A:I0) IC33.2(A:I1) IC40.1(A:I0) IC40.2(A:I1)
IM_01\: IC33.5(B:O) IC40.5(B:O) SV3.J SV8.J
IM_01\_: IC30.4(B:O) IC32.13(D:O) IC33.6(B:I0) IC33.7(B:I1) IC40.6(B:I0) IC40.7(B:I1)
IM_02\: IC34.3(A:O) IC41.3(A:O) SV3.N SV8.N
IM_02\_: IC30.10(C:O) IC34.1(A:I0) IC34.2(A:I1) IC38.1(A:O) IC41.1(A:I0) IC41.2(A:I1)
IM_03\: IC34.5(B:O) IC41.5(B:O) SV3.T SV8.T
IM_03\_: IC30.13(D:O) IC34.6(B:I0) IC34.7(B:I1) IC38.4(B:O) IC41.6(B:I0) IC41.7(B:I1)
IM_04\: IC35.3(A:O) IC42.3(A:O) SV3.X SV8.X
IM_04\_: IC31.1(A:O) IC35.1(A:I0) IC35.2(A:I1) IC38.10(C:O) IC42.1(A:I0) IC42.2(A:I1)
IM_05\: IC35.5(B:O) IC42.5(B:O) SV3.BB SV8.BB
IM_05\_: IC31.4(B:O) IC35.6(B:I0) IC35.7(B:I1) IC38.13(D:O) IC42.6(B:I0) IC42.7(B:I1)
IM_06\: IC36.3(A:O) IC43.3(A:O) SV3.FF SV8.FF
IM_06\_: IC31.10(C:O) IC36.1(A:I0) IC36.2(A:I1) IC39.1(A:O) IC43.1(A:I0) IC43.2(A:I1)
IM_07\: IC36.5(B:O) IC43.5(B:O) SV3.LL SV8.LL
IM_07\_: IC31.13(D:O) IC36.6(B:I0) IC36.7(B:I1) IC39.4(B:O) IC43.6(B:I0) IC43.7(B:I1)
IM_08\: IC37.3(A:O) IC44.3(A:O) SV3.RR SV8.RR
IM_08\_: IC32.1(A:O) IC37.1(A:I0) IC37.2(A:I1) IC39.10(C:O) IC44.1(A:I0) IC44.2(A:I1)
IM_09\: IC37.5(B:O) SV3.F SV8.F
IM_09\_: IC32.4(B:O) IC37.6(B:I0) IC37.7(B:I1)
IM_10\: SV3.L SV8.L
IM_11\: IC44.5(B:O) SV3.R SV8.R
IM_11\_: IC39.13(D:O) IC44.6(B:I0) IC44.7(B:I1)
INT_RQ\: IC16.6(B:O) IC45.5(B:I0)
IOP_1: IC87.5(B:I1) IC88.10(C:I1) SV1.V SV6.V
IOP_2: IC87.10(C:I1) IC88.13(D:I1) SV1.Z SV6.Z
IOP_4: IC87.13(D:I1) IC90.2(A:I1) SV1.DD SV6.DD
LDMF: IC91.6(C:O) IC115.11(B:CLK) IC136.3(A:CLK) IC136.11(B:CLK)
LDMF\: IC61.1(A:I0) IC90.3(A:O) IC91.5(C:I)
LPB_00: IC96.5(2D) IC126.12(A:Q) M916_9.T2
LPB_00\: IC126.13(A:Q\) IC135.1(I0)
LPB_01: IC98.10(1E) IC127.12(A:Q) M916_9.U2
LPB_01\: IC127.13(A:Q\) IC135.2(I1)
LPB_02: IC97.5(2D) IC128.12(A:Q) M916_9.V2
LPB_02\: IC128.13(A:Q\) IC135.3(I2)
LPB_03: IC96.10(1E) IC126.9(B:Q) M916_10.A2
LPB_03\: IC126.8(B:Q\) IC135.4(I3)
LPB_04: IC97.10(1E) IC127.9(B:Q) M916_10.B2
LPB_04\: IC127.8(B:Q\) IC135.5(I4)
LPB_05: IC98.5(2D) IC128.9(B:Q) M916_10.C2
LPB_05\: IC128.8(B:Q\) IC135.6(I5) IC135.11(I6) IC135.12(I7)
LPB_NOT_EQ_1: IC12.5(B:I1) IC135.8(O)
LPB_TO_DTB: IC15.10(E:O) IC96.4(2C) IC96.9(1D) IC97.4(2C) IC97.9(1D) IC98.4(2C) IC98.9(1D)
M-STOP\: IC15.4(B:O) IC76.4(A:PRE) IC95.6(B:CL) ; also sheet 2
MB_TO_DTB\: IC139.1(A:I0) IC139.2(A:I1) IC139.4(A:I2) IC139.5(A:I3) IC139.8(B:O)
MC00: IC73.5(A:Q) IC73.12(B:D) IC133.5(I4) M916_10.S1
MC00\: IC12.13(D:I1) IC69.9(C:I0) IC73.6(A:Q\)
MC01: IC6.11(B:CLK) IC73.9(B:Q) IC74.2(A:D) IC90.13(D:I1) M916_10.T1
MC01\: IC68.3(B:I0) IC73.8(B:Q\) IC90.10(C:I1) IC133.6(I5)
MC02: IC69.10(C:I1) IC74.5(A:Q) IC140.1(A:I0) IC140.2(A:I1) M916_10.U1
MC02\: IC73.2(A:D) IC74.6(A:Q\) IC133.11(I6)
MF00: IC115.9(B:Q) M916_9.V1
MF00\: IC39.2(A:I0) IC46.2(A:I0) IC115.8(B:Q\)
MF01: IC136.5(A:Q) M916_10.A1
MF01\: IC39.5(B:I0) IC46.5(B:I0) IC136.6(A:Q\)
MF02: IC136.9(B:Q) M916_10.B1
MF02\: IC39.8(C:I0) IC46.8(C:I0) IC136.8(B:Q\)
MK_BLK_END: IC10.12(B:I2)
MK_BLK_END\: IC8.4(A:I2)
MK_BLK_MK: IC133.1(I0) IC133.2(I1)
MK_BLK_START\: IC8.1(A:I0)
MK_DATA\: IC8.2(A:I1)
MK_END: IC5.2(A:D)
MK_END\: IC8.5(A:I3)
MKT: IC72.10(B:I1) IC75.9(B:Q) IC78.4(B:I0) IC117.9(C:I0) M916_10.H2
MKT\: IC66.5(A:I3) IC75.8(B:Q\) IC75.12(B:D) IC115.3(A:CLK) IC133.12(I7)
MKTK: IC6.8(B:Q\) M916_9.P1
MKTK\: IC6.9(B:Q) IC10.1(A:I0) IC32.11(D:I0)
MOVE: IC123.10(E:O)
MOVE\: IC9.12(B:I2) IC123.11(E:I) IC124.1
MR00: IC57.9(B:Q) IC76.12(B:D)
MR00\: IC30.11(D:I0) IC57.8(B:Q\)
MR01: IC95.9(B:Q) IC108.2(A:I1) M916_9.E1
MR01\: IC31.2(A:I0) IC76.2(A:D) IC95.8(B:Q\)
N$1: IC55.1(A:I) IC61.3(A:O)
N$2: IC112.10(E:O) IC120.9(B:I0) IC120.10(B:I1) IC120.12(B:I2) IC120.13(B:I3)
N$3: IC15.3(B:I) IC69.6(B:O)
N$5: IC121.6(A:O) M916_2.H2
N$6: IC121.9(B:I0) IC121.10(B:I1) IC121.12(B:I2) IC121.13(B:I3) ; also sheet 2
N$7: IC16.5(B:I1) IC16.11(D:O) IC17.4(B:I0)
N$8: IC123.1(A:I) ; also sheet 2
N$10: IC71.1(A:I0) IC90.8(C:O)
N$11: IC71.5(A:I3) IC90.11(D:O)
N$13: IC61.8(C:O) M916_1.H2 M916_1.J2 M916_1.K2
N$14: M916_2.D2 M916_2.E2
N$15: IC112.13(F:I) M916_2.F2
N$16: IC18.4(A:I2) IC18.5(A:I3) IC112.12(F:O)
N$17: IC77.3(A:CLK) IC77.11(B:CLK) ; also sheet 2
N$18: IC61.11(D:O) M916_1.M2 M916_1.N2 M916_1.P2
N$19: M916_1.H1 M916_1.L2
N$20: M916_2.R2 M916_2.S2
N$21: M916_1.D2 M916_1.E2
N$22: IC15.13(F:I) M916_1.T2
N$23: IC15.5(C:I) M916_1.F2
N$24: IC119.8(B:O) M916_12.K2
N$25: M916_1.R2 M916_1.V2
N$26: M916_1.S1 M916_1.S2
N$28: IC72.2(A:I1) IC109.12(A:O)
N$29: M916_12.D2 M916_12.E2
N$30: IC122.3(B:I) M916_12.F2
N$31: IC19.9(B:I0) IC19.10(B:I1) IC122.4(B:O)
N$32: IC78.8(C:O)
N$33: IC7.10(B:PRE) IC66.6(A:O)
N$34: IC123.9(D:I) ; also sheet 2
N$35: IC8.9(B:I0) IC104.8(1Y)
N$36: IC99.6(C:O) IC115.2(A:D)
N$37: M916_12.R2 M916_12.S2
N$38: IC116.3(A:O) IC116.12(D:I0)
N$39: IC116.6(B:O) IC116.13(D:I1)
N$42: IC106.6(B:O) IC106.12(D:I0)
N$43: IC17.3(A:O) IC17.12(D:I0)
N$44: IC72.13(B:I3) IC106.11(D:O)
N$45: IC17.8(C:O) IC17.13(D:I1)
N$46: IC8.12(B:I2) IC11.11(D:O)
N$47: IC68.8(C:O) IC99.5(C:I)
N$48: IC71.6(A:O) IC107.4(B:I0)
N$49: IC68.10(C:I1) IC70.8(B:O)
N$50: IC110.12(A:O) IC117.12(D:I0)
N$51: IC72.8(B:O) IC108.4(B:I1)
N$52: IC107.6(B:O) IC108.3(B:I0)
N$53: IC117.6(B:O) IC117.13(D:I1)
N$54: IC106.3(A:O) IC108.5(B:I2)
N$55: IC68.9(C:I0) IC70.6(A:O)
N$56: IC2.6(B:O) IC68.11(C:I2)
N$58: IC15.9(D:I) IC61.6(B:O)
N$59: IC107.11(D:O) IC112.3(B:I)
N$60: IC72.1(A:I0) IC108.8(C:O)
N$61: IC72.4(A:I2) IC110.6(B:O)
N$62: IC71.8(B:O) IC72.5(A:I3)
N$63: IC74.10(B:PRE) IC78.3(A:O)
N$64: IC16.8(C:O) IC65.4(A:I2) IC65.5(A:I3)
N$65: IC107.8(C:O) IC107.12(D:I0)
N$66: IC16.3(A:O) IC65.1(A:I0) IC65.2(A:I1)
N$67: IC134.8(O) ; also sheet 2
N$70: IC2.9(C:I0) IC68.6(B:O)
N$71: IC78.6(B:O) IC122.1(A:I)
N$72: IC2.11(C:I2) IC68.12(A:O)
N$73: IC60.6(B:O) IC63.10(B:PRE)
N$76: IC114.11(B:CLK) IC118.3(A:O)
N$77: IC2.8(C:O) IC65.9(B:I0)
N$78: IC65.13(B:I3) IC122.2(A:O)
N$79: IC111.10(E:O) IC114.10(B:PRE)
N$80: IC8.13(B:I3) M916_15.U2
N$81: IC108.12(A:O) IC111.11(E:I)
N$82: IC69.8(C:O) IC122.5(C:I)
N$83: IC5.12(B:D) IC8.8(B:O)
N$84: IC11.3(A:O) IC11.4(B:I0)
N$85: IC11.2(A:I1) IC11.6(B:O) IC78.12(D:I0)
N$86: IC69.13(A:I2) IC78.11(D:O)
N$91: IC60.11(D:O) IC64.4(A:PRE)
N$92: IC59.11(D:O) IC62.10(B:PRE)
N$93: IC126.3(A:K) IC126.14(A:J) IC129.6(2Y)
N$94: IC126.7(B:J) IC126.10(B:K) IC129.8(1Y)
N$95: IC127.3(A:K) IC127.14(A:J) IC131.8(1Y)
N$96: IC128.3(A:K) IC128.14(A:J) IC130.6(2Y)
N$97: IC59.3(A:O) IC62.4(A:PRE)
N$99: IC128.7(B:J) IC128.10(B:K) IC131.6(2Y)
N$100: IC127.7(B:J) IC127.10(B:K) IC130.8(1Y)
N$101: IC123.6(C:O) IC126.5(B:CLK) IC127.5(B:CLK) IC128.5(B:CLK)
N$103: IC122.12(F:O) IC126.1(A:CLK) IC127.1(A:CLK) IC128.1(A:CLK)
N$104: IC96.8(1Y) IC101.10(B:PRE)
N$105: IC4.9(D:I) IC8.6(A:O)
N$106: IC4.8(D:O) IC9.13(B:I3)
N$107: IC6.12(B:D) IC9.8(B:O)
N$108: IC103.8(1Y) IC122.13(F:I)
N$109: IC105.6(2Y) IC123.5(C:I)
N$111: IC10.13(B:I3) IC123.4(B:O)
N$112: IC59.6(B:O) IC64.10(B:PRE)
N$113: IC59.8(C:O) IC63.4(A:PRE)
N$114: IC10.8(B:O) IC15.11(E:I)
N$115: IC117.8(C:O) IC123.3(B:I)
N$116: IC112.5(C:I) IC117.3(A:O)
N$117: IC109.6(B:O) IC140.12(B:I2) IC140.13(B:I3)
N$118: IC106.8(C:O) IC140.9(B:I0) IC140.10(B:I1)
N$119: IC112.1(A:I) IC116.8(C:O)
N$123: M916_3.D2 M916_3.J2
N$124: IC4.11(E:I) IC12.11(D:O)
N$125: IC7.2(A:D) IC12.6(B:O)
N$126: M916_3.E2 M916_3.K2
N$127: M916_13.D2 M916_13.J2
N$128: IC4.10(E:O) IC7.3(A:CLK)
N$129: IC98.6(2Y) IC102.10(B:PRE)
N$130: M916_13.E2 M916_13.K2
N$131: M916_4.D2 M916_4.J2
N$132: IC4.12(F:O) IC6.4(A:PRE)
N$133: M916_4.E2 M916_4.K2
N$134: M916_14.D2 M916_14.J2
N$135: M916_14.E2 M916_14.K2
N$136: M916_5.D2 M916_5.J2
N$137: IC4.13(F:I) IC13.6(B:O)
N$138: IC9.6(A:O) IC13.5(B:I1)
N$139: IC13.3(A:O) IC13.4(B:I0)
N$140: M916_5.E2 M916_5.K2
N$142: IC97.8(1Y) IC102.4(A:PRE)
N$146: IC96.6(2Y) IC100.4(A:PRE)
N$147: IC98.8(1Y) IC100.10(B:PRE)
N$148: IC97.6(2Y) IC101.4(A:PRE)
N$153: IC11.8(C:O) IC12.2(A:I1)
N$155: IC105.8(1Y) IC113.12(B:D)
N$161: IC10.6(A:O) IC14.1(A:I)
N$162: IC13.10(C:I1) IC13.12(D:I0) IC14.2(A:O)
N$185: IC103.6(2Y) IC113.2(A:D)
N$193: IC104.6(2Y) IC114.2(A:D)
NC: M916_3.H2 M916_3.L2 M916_3.M2 M916_4.H2 M916_4.L2 M916_4.M2 M916_5.H2 M916_5.L2 M916_5.M2 M916_8.A2 M916_8.B2 M916_8.J2 M916_13.H2 M916_13.L2 M916_13.M2 M916_14.H2 M916_14.L2 M916_14.M2 M916_16.R2 SV3.NN SV3.TT SV4.L SV4.NN SV4.R SV4.TT SV8.NN SV8.TT SV9.L SV9.NN SV9.R SV9.TT ; also sheet 2
PAR: IC7.6(A:Q\) M916_9.T1
PAR\: IC7.5(A:Q) IC13.13(D:I1) IC38.8(C:I0)
PC+ES: IC13.8(C:O) IC14.9(D:I)
PC+ES\: IC14.8(D:O) IC69.5(B:I2)
PWR_CLR: IC93.6(C:O)
PWR_CLR\: IC12.1(A:I0) IC12.10(C:I1) IC13.9(C:I0) IC61.5(B:I1) IC90.6(B:O) IC93.5(C:I) IC107.13(D:I1) IC115.4(A:PRE) IC115.13(B:CLR) IC136.1(A:CLR) IC136.13(B:CLR) M916_7.M1
RD+WD: IC9.4(A:I2) IC60.8(C:O) IC71.9(B:I0) IC109.2(A:I1)
RD_EN: IC106.5(B:I1) IC107.3(A:O)
RD_EN_LPB_00-02: IC103.1(1A) IC112.6(C:O) IC129.5(2D) IC130.5(2D) IC131.10(1E)
RD_EN_LPB_03-05: IC105.2(2A) IC112.2(A:O) IC129.10(1E) IC130.10(1E) IC131.5(2D)
RDD_00: IC63.12(B:D) IC129.4(2C) IC129.9(1D) M916_5.U2
RDD_00\: M916_5.V2
RDD_01: IC64.2(A:D) IC130.9(1D) IC131.9(1D) M916_14.U2
RDD_01\: M916_14.V2
RDD_02: IC62.12(B:D) IC130.4(2C) IC131.4(2C) M916_4.U2
RDD_02\: M916_4.V2
RDMK: M916_13.U2
RDMK\: M916_13.V2
READ_ALL: IC125.4(B:O)
READ_ALL\: IC106.13(D:I1) IC124.4 IC125.3(B:I)
READ_DATA: IC12.4(B:I0) IC106.4(B:I0) IC125.2(A:O)
READ_DATA\: IC60.9(C:I0) IC69.1(A:I0) IC124.3 IC125.1(A:I)
RSTA: IC55.8(D:O)
RSTA\: IC30.3(A:I1) IC30.6(B:I1) IC30.9(C:I1) IC30.12(D:I1) IC31.3(A:I1) IC31.6(B:I1) IC31.9(C:I1) IC31.12(D:I1) IC32.3(A:I1) IC32.6(B:I1) IC55.9(D:I) IC87.6(B:O)
RSTB: IC91.4(B:O)
RSTB\: IC32.9(C:I1) IC32.12(D:I1) IC38.3(A:I1) IC38.6(B:I1) IC38.9(C:I1) IC38.12(D:I1) IC39.3(A:I1) IC39.6(B:I1) IC39.9(C:I1) IC39.12(D:I1) IC88.11(D:O) IC91.3(B:I)
SE: IC125.12(F:O)
SE\: IC8.10(B:I1) IC124.8 IC125.13(F:I)
SEARCH: IC106.1(A:I0) IC123.12(F:O)
SEARCH\: IC47.2(A:I0) IC69.2(A:I1) IC123.13(F:I) IC124.2
SEL: IC5.9(B:Q) M916_9.S1
SEL\: IC5.8(B:Q\) IC10.5(A:I3) IC38.5(B:I0)
SH_DTB: IC13.2(A:I1) IC62.3(A:CLK) IC62.11(B:CLK) IC63.3(A:CLK) IC63.11(B:CLK) IC64.3(A:CLK) IC64.11(B:CLK) IC65.6(A:O) IC100.3(A:CLK) IC100.11(B:CLK) IC101.3(A:CLK) IC101.11(B:CLK) IC102.3(A:CLK) IC102.11(B:CLK)
SH_EN: IC15.2(A:O) IC16.2(A:I1) IC103.2(2A) IC104.2(2A) IC105.1(1A)
SH_EN\: IC15.1(A:I) IC17.11(D:O) IC103.4(2C) IC104.4(2C) IC105.9(1D)
SH_ST: IC112.11(E:I)
SH_ST-B: IC120.8(B:O)
SHIFT_CK: IC122.6(C:O)
SKP_RQ\: IC17.6(B:O) IC45.8(C:I0)
SP_DY\: IC114.12(B:D) ; also sheet 2
ST_BLK_MK: IC99.13(F:I) M916_10.K1
ST_BLK_MK\: IC9.1(A:I0) IC9.9(B:I0) IC99.12(F:O)
ST_CK: IC12.12(D:I0) IC111.1(A:I) M916_10.P1 ; also sheet 2
ST_CK\: IC111.2(A:O) IC120.2(A:I1)
ST_CK_0P: IC71.13(B:I3) IC99.4(B:O) IC109.13(A:I2)
ST_CK_0P\: IC99.3(B:I) ; also sheet 2
ST_DATA: IC70.1(A:I0) IC111.3(B:I) IC120.6(A:O)
ST_DATA\: IC111.4(B:O)
ST_FINAL: IC10.10(B:I1) IC90.12(D:I0) M916_10.N1
ST_FINAL\: IC107.2(A:I1) IC120.4(A:I2)
ST_IDLE: IC111.5(C:I) M916_10.R1
ST_IDLE\: IC9.2(A:I1) IC9.10(B:I1) IC111.6(C:O)
ST_REV_CK: IC68.5(B:I2) IC90.9(C:I0) IC99.9(D:I) IC140.4(A:I2) IC140.5(A:I3) M916_10.L1
ST_REV_CK\: IC99.8(D:O)
SWTM: IC2.4(B:I1) IC54.11(E:I) IC55.4(B:O) IC104.10(1E) IC110.2(A:I1) IC117.4(B:I0) M916_10.V2
SWTM\: IC54.10(E:O) IC104.12(1B)
SYNC: IC66.9(B:I0) IC66.10(B:I1)
SYNC-P\: IC66.8(B:O) IC73.1(A:CLR) IC73.13(B:CLR) IC74.1(A:CLR) IC74.13(B:CLR) IC75.1(A:CLR) IC75.13(B:CLR)
SYNC_EN: IC69.12(A:O)
T3: IC123.2(A:O) IC139.10(B:I1) IC139.12(B:I2)
T_00\: M916_8.V2 M916_16.V2 M916_17.V2
T_01\: M916_7.S1 M916_8.M2 M916_17.M2
T_02\: M916_7.H2 M916_8.N2 M916_17.N2
T_03\: M916_7.J2 M916_8.P2 M916_17.P2
T_04\: M916_7.N2 M916_8.R2 M916_17.R2
T_05\: M916_7.P2 M916_8.S2 M916_17.S2
T_06\: M916_7.U2 M916_8.T2 M916_17.T2
T_07\: M916_7.V2 M916_8.U2 M916_17.U2
T_FWD\: M916_7.K1 M916_8.E2 M916_17.H2
T_GO\: M916_8.C2 M916_17.D2
T_PWR_CLR\: M916_7.R1 M916_8.H2 M916_17.K2
T_REV\: M916_7.L1 M916_8.F2 M916_17.J2
T_SINGLE_UNIT\: M916_8.K2 M916_15.T2
T_STOP\: M916_7.E1 M916_8.D2 M916_17.E2
T_TRK: IC61.13(D:I1) IC118.2(A:I1) M916_3.U2 ; also sheet 2
T_TRK\: IC61.10(C:I1) M916_3.V2
T_WRITE_OK\: M916_6.H2 M916_8.L2 M916_17.L2
TIM: IC6.5(A:Q) M916_9.U1
TIM\: IC6.6(A:Q\) IC10.2(A:I1) IC38.11(D:I0)
TM_EN: IC111.9(D:I) IC117.11(D:O) IC119.9(B:I0) IC121.1(A:I0) M916_3.R2 M916_13.R2
TM_EN\: IC61.9(C:I0) IC61.12(D:I0) IC108.13(A:I2) IC109.10(C:I1) IC111.8(D:O) ; also sheet 2
TP00: IC5.3(A:CLK) IC18.8(B:O) IC66.2(A:I1) IC66.12(B:I2) IC66.13(B:I3) IC73.3(A:CLK) IC73.11(B:CLK) IC74.3(A:CLK) IC78.2(A:I1) IC116.5(B:I1) M916_2.M2 M916_2.N2 M916_2.P2
TP00\: IC18.6(A:O) IC18.9(B:I0) IC18.10(B:I1) IC18.12(B:I2) IC18.13(B:I3) IC75.3(A:CLK)
TP00_A: IC19.6(A:O) IC65.10(B:I1) IC109.4(B:I1)
TP00_A\: IC19.1(A:I0) IC19.2(A:I1) IC19.4(A:I2) IC19.5(A:I3) M916_2.L2
TP0_XTLK_DY\: IC15.6(C:O) IC19.12(B:I2) M916_2.J2 M916_2.K2
TP01: IC16.10(C:I1) IC20.6(A:O) IC106.10(C:I1) IC116.2(A:I1) M916_12.M2 M916_12.N2 M916_12.P2
TP01\: IC19.8(B:O) IC20.1(A:I0) IC20.2(A:I1) IC20.4(A:I2) IC20.5(A:I3) IC74.11(B:CLK)
TP01_A: IC20.8(B:O) IC72.12(B:I2) IC117.10(C:I1)
TP01_A\: IC20.9(B:I0) IC20.10(B:I1) IC20.12(B:I2) IC20.13(B:I3) M916_12.L2
TP1_XTLK_DY\: IC15.12(F:O) IC18.2(A:I1) M916_12.H2 M916_12.J2
TS03\: IC88.3(A:O) ; also sheet 2
U+M_DY\: IC108.1(A:I0) IC110.13(A:I2) ; also sheet 2
USR_00: IC1.22(B) IC56.12(A:Q) M916_9.A1
USR_00\: IC30.2(A:I0) IC56.13(A:Q\)
USR_01: IC1.21(C) IC56.9(B:Q) M916_9.B1
USR_01\: IC30.5(B:I0) IC56.8(B:Q\)
USR_02: IC1.20(D) IC57.12(A:Q) M916_9.C1
USR_02\: IC30.8(C:I0) IC57.13(A:Q\)
USR_02_: IC1.18(G1) IC1.19(G2) IC2.12(A:O)
UTS: IC11.5(B:I1) IC78.9(C:I0) IC114.8(B:Q\) M916_10.J1
UTS\: IC67.9(B:I0) IC67.10(B:I1) IC67.12(B:I2) IC67.13(B:I3) IC109.11(C:I2) IC114.9(B:Q) IC118.1(A:I0) IC119.1(A:I0) IC119.2(A:I1) IC119.4(A:I2) IC119.5(A:I3)
VCC: IC96.11(1F) IC96.13(1C) IC97.11(1F) IC97.13(1C) IC98.11(1F) IC98.13(1C) IC103.11(1F) IC103.13(1C) IC104.11(1F) IC104.13(1C) IC105.11(1F) IC105.13(1C) IC129.11(1F) IC129.13(1C) IC130.11(1F) IC130.13(1C) IC131.11(1F) IC131.13(1C) M916_1.A2 M916_2.A2 M916_3.A2 M916_4.A2 M916_5.A2 M916_6.A2 M916_7.A2 M916_12.A2 M916_13.A2 M916_14.A2 M916_15.A2 M916_16.A2 ; also sheet 2
W01: M916_10.J2
W02: M916_10.K2
W03: M916_10.L2
W04: M916_10.M2
W05: M916_10.N2
W06: M916_10.P2
W07: M916_10.R2
W08: M916_10.S2
W09: M916_10.T2
W+UTS: IC18.1(A:I0) IC19.13(B:I3) IC109.8(C:O)
W-INH: IC7.8(B:Q\)
W-INH\: IC7.9(B:Q) IC68.2(A:I1) IC70.10(B:I1)
WB00: IC113.6(A:Q\) IC129.2(2A) M916_5.N2 M916_9.P2 M916_13.N2
WB00\: IC103.5(2D) IC113.5(A:Q) M916_5.P2 M916_13.P2
WB01: IC113.8(B:Q\) IC131.1(1A) M916_9.R2 M916_14.N2
WB01\: IC105.10(1E) IC113.9(B:Q) M916_14.P2
WB02: IC114.6(A:Q\) IC130.2(2A) M916_4.N2 M916_9.S2
WB02\: IC104.5(2D) IC114.5(A:Q) M916_4.P2
WC: IC66.1(A:I0) IC68.1(A:I0) IC137.9(B:Q) M916_10.H1
WC0: IC79.8(C:O) IC93.1(A:I)
WC0\: IC93.2(A:O) IC137.10(B:PRE)
WC\: IC71.12(B:I2) IC110.3(B:I0) IC137.2(A:D) IC137.8(B:Q\)
WR_EN: IC103.10(1E) IC105.5(2D) IC109.3(B:I0) IC115.6(A:Q\) IC116.1(A:I0) IC117.5(B:I1) IC129.3(2B) IC129.12(1B) IC130.3(2B) IC130.12(1B) IC131.3(2B) IC131.12(1B) M916_4.R2 M916_5.R2 M916_10.F1 M916_14.R2
WR_EN\: IC2.10(C:I1) IC106.9(C:I0) IC109.9(C:I0) IC115.5(A:Q) IC116.9(C:I0) IC117.1(A:I0)
WRITE_ALL: IC7.11(B:CLK) IC68.13(A:I2) IC70.9(B:I0) IC125.8(D:O)
WRITE_ALL\: IC124.6 IC125.9(D:I)
WRITE_DATA: IC10.9(B:I0) IC68.4(B:I1) IC70.2(A:I1) IC71.4(A:I2) IC125.6(C:O)
WRITE_DATA\: IC60.10(C:I1) IC124.5 IC125.5(C:I)
WRITE_OK: IC2.5(B:I2) IC78.10(C:I1) IC122.9(D:I) M916_6.D2
WRITE_OK+UTS: IC70.5(A:I3) IC70.13(B:I3)
WRITE_OK\: IC11.13(D:I1) IC122.8(D:O)
WRTM: IC2.3(B:I0) IC104.1(1A) IC110.1(A:I0) IC125.10(E:O)
WRTM+FR03: IC60.3(A:O) IC108.11(C:I2) IC110.5(B:I2)
WRTM\: IC60.1(A:I0) IC104.9(1D) IC124.7 IC125.11(E:I)
XOR_TO_LPB: IC103.9(1D) IC103.12(1B) IC105.3(2B) IC105.4(2C) IC140.8(B:O)
XSA_DY: IC5.11(B:CLK) IC76.3(A:CLK) IC76.11(B:CLK) IC123.8(D:O)
XSAD: IC9.5(A:I3) IC14.10(E:O)
XSAD\: IC14.11(E:I) ; also sheet 2
XSTA: IC55.12(F:O) IC56.1(A:CLK) IC56.5(B:CLK) IC57.1(A:CLK) IC57.5(B:CLK) IC58.1(A:CLK) IC58.5(B:CLK) IC94.1(A:CLK) IC94.5(B:CLK) IC95.1(A:CLK) IC95.5(B:CLK) IC137.11(B:CLK) ; also sheet 2
XSTA\: IC55.13(F:I) IC61.2(A:I1) IC87.11(D:O) ; also sheet 2
Unconnected: IC1.9 IC1.10 IC1.11 IC1.13 IC1.14 IC1.15 IC1.16 IC1.17 IC47.4(B:O) IC47.5(B:I0) IC47.6(B:I1) IC47.8(C:I0) IC47.9(C:I1) IC47.10(C:O) IC47.11(D:I0) IC47.12(D:I1) IC47.13(D:O) IC52.5(B:O) IC52.6(B:I0) IC52.7(B:I1) IC118.4(B:I0) IC118.5(B:I1) IC118.6(B:O) IC118.8(C:O) IC118.9(C:I0) IC118.10(C:I1) IC118.11(D:O) IC118.12(D:I0) IC118.13(D:I1) IC124.9 IC124.10 IC124.11 IC124.13 IC124.14 IC124.15 IC124.16 IC124.17 IC132.5(C:I) IC132.6(C:O) IC132.8(D:O) IC132.9(D:I) IC132.10(E:O) IC132.11(E:I) IC132.12(F:O) IC132.13(F:I) IC138.8(B:Q\) IC138.9(B:Q) IC138.10(B:PRE) IC138.11(B:CLK) IC138.12(B:D) IC138.13(B:CLR) IC141.8(B:O) IC141.9(B:I0) IC141.10(B:I1) IC141.12(B:I2) IC141.13(B:I3) M916_1.A1 M916_1.B1 M916_1.B2 M916_1.C1 M916_1.D1 M916_1.E1 M916_1.F1 M916_1.J1 M916_1.K1 M916_1.L1 M916_1.M1 M916_1.N1 M916_1.P1 M916_1.R1 M916_1.U1 M916_1.U2 M916_1.V1 M916_2.A1 M916_2.B1 M916_2.B2 M916_2.C1 M916_2.D1 M916_2.E1 M916_2.F1 M916_2.H1 M916_2.J1 M916_2.K1 M916_2.L1 M916_2.M1 M916_2.N1 M916_2.P1 M916_2.R1 M916_2.S1 M916_2.T2 M916_2.U1 M916_2.U2 M916_2.V1 M916_2.V2 M916_3.A1 M916_3.B1 M916_3.C1 M916_3.D1 M916_3.E1 M916_3.F1 M916_3.F2 M916_3.H1 M916_3.J1 M916_3.K1 M916_3.L1 M916_3.M1 M916_3.N1 M916_3.P1 M916_3.R1 M916_3.S1 M916_3.S2 M916_3.T1 M916_3.T2 M916_3.U1 M916_3.V1 M916_4.A1 M916_4.B1 M916_4.C1 M916_4.D1 M916_4.E1 M916_4.F1 M916_4.F2 M916_4.H1 M916_4.J1 M916_4.K1 M916_4.L1 M916_4.M1 M916_4.N1 M916_4.P1 M916_4.R1 M916_4.S1 M916_4.S2 M916_4.T1 M916_4.T2 M916_4.U1 M916_4.V1 M916_5.A1 M916_5.B1 M916_5.C1 M916_5.D1 M916_5.E1 M916_5.F1 M916_5.F2 M916_5.H1 M916_5.J1 M916_5.K1 M916_5.L1 M916_5.M1 M916_5.N1 M916_5.P1 M916_5.R1 M916_5.S1 M916_5.S2 M916_5.T1 M916_5.T2 M916_5.U1 M916_5.V1 M916_6.A1 M916_6.B1 M916_6.C1 M916_6.D1 M916_6.E1 M916_6.E2 M916_6.F1 M916_6.F2 M916_6.H1 M916_6.J1 M916_6.J2 M916_6.K1 M916_6.K2 M916_6.L1 M916_6.L2 M916_6.M1 M916_6.N1 M916_6.N2 M916_6.P1 M916_6.P2 M916_6.R1 M916_6.R2 M916_6.S1 M916_6.S2 M916_6.T1 M916_6.T2 M916_6.U1 M916_6.U2 M916_6.V1 M916_6.V2 M916_7.D1 M916_8.A1 M916_8.B1 M916_8.C1 M916_8.D1 M916_8.E1 M916_8.F1 M916_8.H1 M916_8.J1 M916_8.K1 M916_8.L1 M916_8.M1 M916_8.N1 M916_8.P1 M916_8.R1 M916_8.S1 M916_8.T1 M916_8.U1 M916_8.V1 M916_9.D1 M916_10.D1 M916_12.A1 M916_12.B1 M916_12.B2 M916_12.C1 M916_12.D1 M916_12.E1 M916_12.F1 M916_12.H1 M916_12.J1 M916_12.K1 M916_12.L1 M916_12.M1 M916_12.N1 M916_12.P1 M916_12.R1 M916_12.S1 M916_12.T2 M916_12.U1 M916_12.U2 M916_12.V1 M916_12.V2 M916_13.A1 M916_13.B1 M916_13.C1 M916_13.D1 M916_13.E1 M916_13.F1 M916_13.F2 M916_13.H1 M916_13.J1 M916_13.K1 M916_13.L1 M916_13.M1 M916_13.N1 M916_13.P1 M916_13.R1 M916_13.S1 M916_13.S2 M916_13.T1 M916_13.T2 M916_13.U1 M916_13.V1 M916_14.A1 M916_14.B1 M916_14.C1 M916_14.D1 M916_14.E1 M916_14.F1 M916_14.F2 M916_14.H1 M916_14.J1 M916_14.K1 M916_14.L1 M916_14.M1 M916_14.N1 M916_14.P1 M916_14.R1 M916_14.S1 M916_14.S2 M916_14.T1 M916_14.T2 M916_14.U1 M916_14.V1 M916_15.A1 M916_15.B1 M916_15.C1 M916_15.D1 M916_15.D2 M916_15.E1 M916_15.E2 M916_15.F1 M916_15.F2 M916_15.H1 M916_15.H2 M916_15.J1 M916_15.J2 M916_15.K1 M916_15.K2 M916_15.L1 M916_15.L2 M916_15.M1 M916_15.M2 M916_15.N1 M916_15.N2 M916_15.P1 M916_15.P2 M916_15.R1 M916_15.R2 M916_15.S1 M916_15.S2 M916_15.T1 M916_15.U1 M916_15.V1 M916_15.V2 M916_16.A1 M916_16.B1 M916_16.C1 M916_16.D1 M916_16.D2 M916_16.E1 M916_16.E2 M916_16.F1 M916_16.F2 M916_16.H1 M916_16.H2 M916_16.J1 M916_16.J2 M916_16.K1 M916_16.K2 M916_16.L1 M916_16.L2 M916_16.M1 M916_16.M2 M916_16.N1 M916_16.N2 M916_16.P1 M916_16.P2 M916_16.R1 M916_16.S1 M916_16.U2 M916_17.A1 M916_17.A2 M916_17.B1 M916_17.C1 M916_17.D1 M916_17.E1 M916_17.F1 M916_17.F2 M916_17.H1 M916_17.J1 M916_17.K1 M916_17.L1 M916_17.M1 M916_17.N1 M916_17.P1 M916_17.R1 M916_17.S1 M916_17.T1 M916_17.U1 M916_17.V1

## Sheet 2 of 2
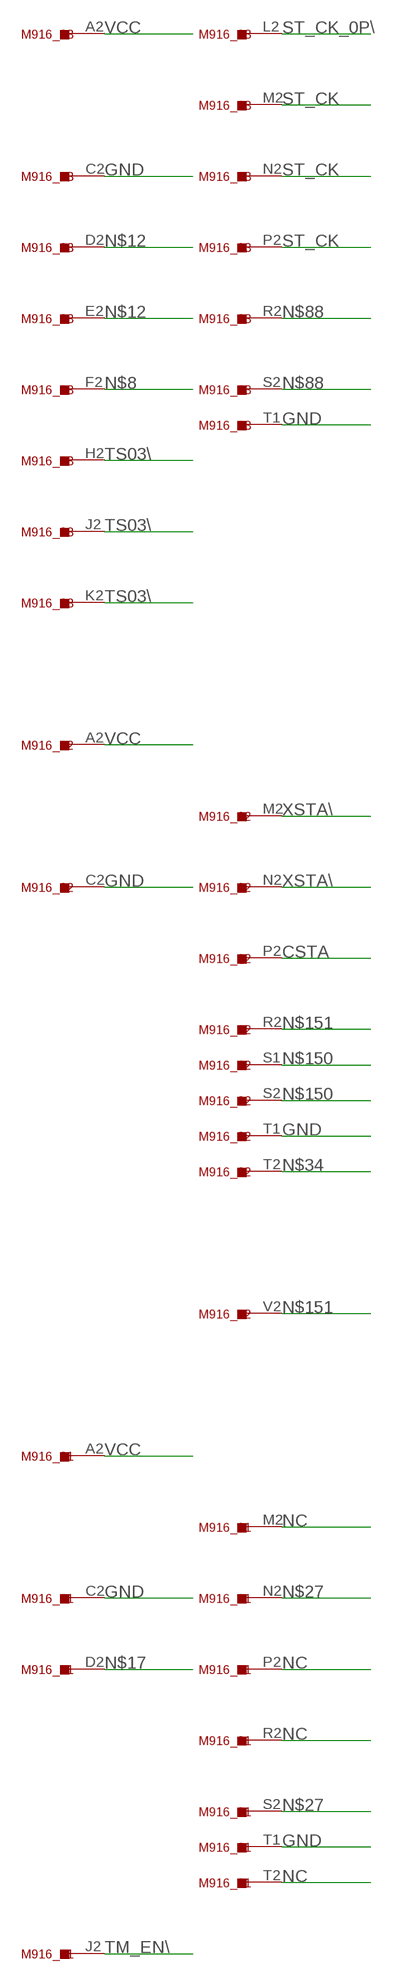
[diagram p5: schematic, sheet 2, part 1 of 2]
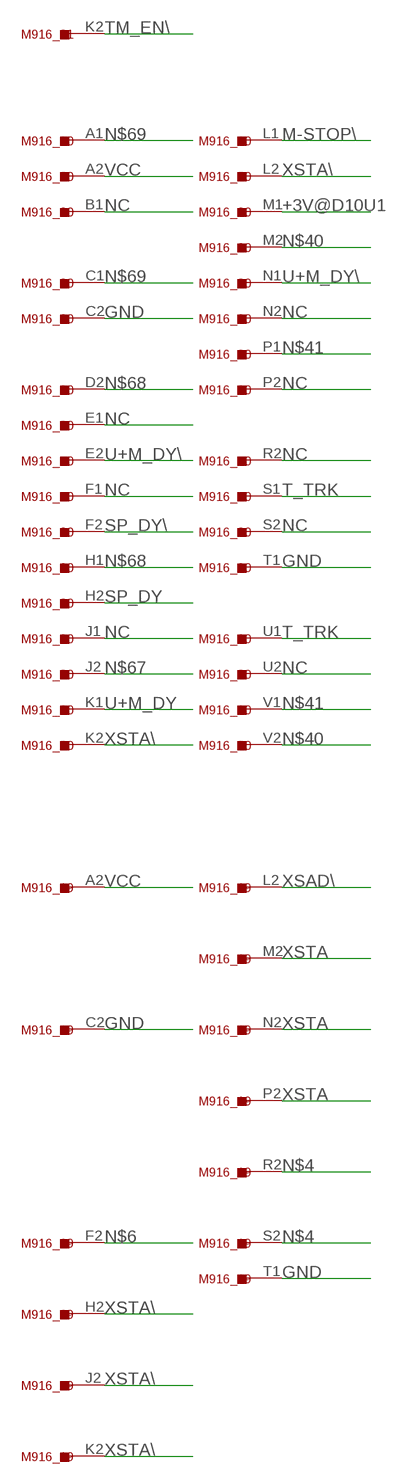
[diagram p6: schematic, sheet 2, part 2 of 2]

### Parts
M916_19  M602  M916  [H807]
M916_20  M307  M916  [H807]
M916_21  M401  M916  [H807]
M916_22  M302  M916  [H807]
M916_23  M602  M916  [H807]

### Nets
+3V@D10U1: M916_20.M1 ; also sheet 1
CSTA: M916_22.P2 ; also sheet 1
GND: M916_19.C2 M916_19.T1 M916_20.C2 M916_20.T1 M916_21.C2 M916_21.T1 M916_22.C2 M916_22.T1 M916_23.C2 M916_23.T1 ; also sheet 1
M-STOP\: M916_20.L1 ; also sheet 1
N$4: M916_19.R2 M916_19.S2
N$6: M916_19.F2 ; also sheet 1
N$8: M916_23.F2 ; also sheet 1
N$12: M916_23.D2 M916_23.E2
N$17: M916_21.D2 ; also sheet 1
N$27: M916_21.N2 M916_21.S2
N$34: M916_22.T2 ; also sheet 1
N$40: M916_20.M2 M916_20.V2
N$41: M916_20.P1 M916_20.V1
N$67: M916_20.J2 ; also sheet 1
N$68: M916_20.D2 M916_20.H1
N$69: M916_20.A1 M916_20.C1
N$88: M916_23.R2 M916_23.S2
N$150: M916_22.S1 M916_22.S2
N$151: M916_22.R2 M916_22.V2
NC: M916_20.B1 M916_20.E1 M916_20.F1 M916_20.J1 M916_20.N2 M916_20.P2 M916_20.R2 M916_20.S2 M916_20.U2 M916_21.M2 M916_21.P2 M916_21.R2 M916_21.T2 ; also sheet 1
SP_DY: M916_20.H2
SP_DY\: M916_20.F2 ; also sheet 1
ST_CK: M916_23.M2 M916_23.N2 M916_23.P2 ; also sheet 1
ST_CK_0P\: M916_23.L2 ; also sheet 1
T_TRK: M916_20.S1 M916_20.U1 ; also sheet 1
TM_EN\: M916_21.J2 M916_21.K2 ; also sheet 1
TS03\: M916_23.H2 M916_23.J2 M916_23.K2 ; also sheet 1
U+M_DY: M916_20.K1
U+M_DY\: M916_20.E2 M916_20.N1 ; also sheet 1
VCC: M916_19.A2 M916_20.A2 M916_21.A2 M916_22.A2 M916_23.A2 ; also sheet 1
XSAD\: M916_19.L2 ; also sheet 1
XSTA: M916_19.M2 M916_19.N2 M916_19.P2 ; also sheet 1
XSTA\: M916_19.H2 M916_19.J2 M916_19.K2 M916_20.K2 M916_20.L2 M916_22.M2 M916_22.N2 ; also sheet 1
Unconnected: M916_19.A1 M916_19.B1 M916_19.B2 M916_19.C1 M916_19.D1 M916_19.D2 M916_19.E1 M916_19.E2 M916_19.F1 M916_19.H1 M916_19.J1 M916_19.K1 M916_19.L1 M916_19.M1 M916_19.N1 M916_19.P1 M916_19.R1 M916_19.S1 M916_19.T2 M916_19.U1 M916_19.U2 M916_19.V1 M916_19.V2 M916_20.B2 M916_20.D1 M916_20.R1 M916_20.T2 M916_21.A1 M916_21.B1 M916_21.B2 M916_21.C1 M916_21.D1 M916_21.E1 M916_21.E2 M916_21.F1 M916_21.F2 M916_21.H1 M916_21.H2 M916_21.J1 M916_21.K1 M916_21.L1 M916_21.L2 M916_21.M1 M916_21.N1 M916_21.P1 M916_21.R1 M916_21.S1 M916_21.U1 M916_21.U2 M916_21.V1 M916_21.V2 M916_22.A1 M916_22.B1 M916_22.B2 M916_22.C1 M916_22.D1 M916_22.D2 M916_22.E1 M916_22.E2 M916_22.F1 M916_22.F2 M916_22.H1 M916_22.H2 M916_22.J1 M916_22.J2 M916_22.K1 M916_22.K2 M916_22.L1 M916_22.L2 M916_22.M1 M916_22.N1 M916_22.P1 M916_22.R1 M916_22.U1 M916_22.U2 M916_22.V1 M916_23.A1 M916_23.B1 M916_23.B2 M916_23.C1 M916_23.D1 M916_23.E1 M916_23.F1 M916_23.H1 M916_23.J1 M916_23.K1 M916_23.L1 M916_23.M1 M916_23.N1 M916_23.P1 M916_23.R1 M916_23.S1 M916_23.T2 M916_23.U1 M916_23.U2 M916_23.V1 M916_23.V2

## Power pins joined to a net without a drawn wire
GND: IC1.12(GND) IC2.7(P:GND) IC3.7(P:GND) IC4.7(P:GND) IC5.7(P:GND) IC6.7(P:GND) IC7.7(P:GND) IC8.7(P:GND) IC9.7(P:GND) IC10.7(P:GND) IC11.7(P:GND) IC12.7(P:GND) IC13.7(P:GND) IC14.7(P:GND) IC15.7(P:GND) IC16.7(P:GND) IC17.7(P:GND) IC18.7(P:GND) IC19.7(P:GND) IC20.7(P:GND) IC21.7(P:GND) IC22.7(P:GND) IC23.7(P:GND) IC24.4(P:GND) IC25.4(P:GND) IC26.4(P:GND) IC27.4(P:GND) IC28.4(P:GND) IC29.4(P:GND) IC30.7(P:GND) IC31.7(P:GND) IC32.7(P:GND) IC33.4(P:GND) IC34.4(P:GND) IC35.4(P:GND) IC36.4(P:GND) IC37.4(P:GND) IC38.7(P:GND) IC39.7(P:GND) IC40.4(P:GND) IC41.4(P:GND) IC42.4(P:GND) IC43.4(P:GND) IC44.4(P:GND) IC45.7(P:GND) IC46.7(P:GND) IC47.7(P:GND) IC48.4(P:GND) IC49.4(P:GND) IC50.4(P:GND) IC51.4(P:GND) IC52.4(P:GND) IC53.7(P:GND) IC54.7(P:GND) IC55.7(P:GND) IC56.11(P:GND) IC57.11(P:GND) IC58.11(P:GND) IC59.7(P:GND) IC60.7(P:GND) IC61.7(P:GND) IC62.7(P:GND) IC63.7(P:GND) IC64.7(P:GND) IC65.7(P:GND) IC66.7(P:GND) IC67.7(P:GND) IC68.7(P:GND) IC69.7(P:GND) IC70.7(P:GND) IC71.7(P:GND) IC72.7(P:GND) IC73.7(P:GND) IC74.7(P:GND) IC75.7(P:GND) IC76.7(P:GND) IC77.7(P:GND) IC78.7(P:GND) IC79.7(P:GND) IC80.7(P:GND) IC81.7(P:GND) IC82.7(P:GND) IC83.7(P:GND) IC84.7(P:GND) IC85.7(P:GND) IC86.7(GND) IC87.7(P:GND) IC88.7(P:GND) IC89.7(GND) IC90.7(P:GND) IC91.7(P:GND) IC92.7(P:GND) IC93.7(P:GND) IC94.11(P:GND) IC95.11(P:GND) IC96.7(GND) IC97.7(GND) IC98.7(GND) IC99.7(P:GND) IC100.7(P:GND) IC101.7(P:GND) IC102.7(P:GND) IC103.7(GND) IC104.7(GND) IC105.7(GND) IC106.7(P:GND) IC107.7(P:GND) IC108.7(P:GND) IC109.7(P:GND) IC110.7(P:GND) IC111.7(P:GND) IC112.7(P:GND) IC113.7(P:GND) IC114.7(P:GND) IC115.7(P:GND) IC116.7(P:GND) IC117.7(P:GND) IC118.7(P:GND) IC119.7(P:GND) IC120.7(P:GND) IC121.7(P:GND) IC122.7(P:GND) IC123.7(P:GND) IC124.12(GND) IC125.7(P:GND) IC126.11(P:GND) IC127.11(P:GND) IC128.11(P:GND) IC129.7(GND) IC130.7(GND) IC131.7(GND) IC132.7(P:GND) IC133.7(GND) IC134.7(GND) IC135.7(GND) IC136.7(P:GND) IC137.7(P:GND) IC138.7(P:GND) IC139.7(P:GND) IC140.7(P:GND) IC141.7(P:GND)
VCC: IC1.24(VCC) IC2.14(P:VCC) IC3.14(P:VCC) IC4.14(P:VCC) IC5.14(P:VCC) IC6.14(P:VCC) IC7.14(P:VCC) IC8.14(P:VCC) IC9.14(P:VCC) IC10.14(P:VCC) IC11.14(P:VCC) IC12.14(P:VCC) IC13.14(P:VCC) IC14.14(P:VCC) IC15.14(P:VCC) IC16.14(P:VCC) IC17.14(P:VCC) IC18.14(P:VCC) IC19.14(P:VCC) IC20.14(P:VCC) IC21.14(P:VCC) IC22.14(P:VCC) IC23.14(P:VCC) IC24.8(P:VCC) IC25.8(P:VCC) IC26.8(P:VCC) IC27.8(P:VCC) IC28.8(P:VCC) IC29.8(P:VCC) IC30.14(P:VCC) IC31.14(P:VCC) IC32.14(P:VCC) IC33.8(P:VCC) IC34.8(P:VCC) IC35.8(P:VCC) IC36.8(P:VCC) IC37.8(P:VCC) IC38.14(P:VCC) IC39.14(P:VCC) IC40.8(P:VCC) IC41.8(P:VCC) IC42.8(P:VCC) IC43.8(P:VCC) IC44.8(P:VCC) IC45.14(P:VCC) IC46.14(P:VCC) IC47.14(P:VCC) IC48.8(P:VCC) IC49.8(P:VCC) IC50.8(P:VCC) IC51.8(P:VCC) IC52.8(P:VCC) IC53.14(P:VCC) IC54.14(P:VCC) IC55.14(P:VCC) IC56.4(P:VCC) IC57.4(P:VCC) IC58.4(P:VCC) IC59.14(P:VCC) IC60.14(P:VCC) IC61.14(P:VCC) IC62.14(P:VCC) IC63.14(P:VCC) IC64.14(P:VCC) IC65.14(P:VCC) IC66.14(P:VCC) IC67.14(P:VCC) IC68.14(P:VCC) IC69.14(P:VCC) IC70.14(P:VCC) IC71.14(P:VCC) IC72.14(P:VCC) IC73.14(P:VCC) IC74.14(P:VCC) IC75.14(P:VCC) IC76.14(P:VCC) IC77.14(P:VCC) IC78.14(P:VCC) IC79.14(P:VCC) IC80.14(P:VCC) IC81.14(P:VCC) IC82.14(P:VCC) IC83.14(P:VCC) IC84.14(P:VCC) IC85.14(P:VCC) IC86.14(VCC) IC87.14(P:VCC) IC88.14(P:VCC) IC89.14(VCC) IC90.14(P:VCC) IC91.14(P:VCC) IC92.14(P:VCC) IC93.14(P:VCC) IC94.4(P:VCC) IC95.4(P:VCC) IC96.14(VCC) IC97.14(VCC) IC98.14(VCC) IC99.14(P:VCC) IC100.14(P:VCC) IC101.14(P:VCC) IC102.14(P:VCC) IC103.14(VCC) IC104.14(VCC) IC105.14(VCC) IC106.14(P:VCC) IC107.14(P:VCC) IC108.14(P:VCC) IC109.14(P:VCC) IC110.14(P:VCC) IC111.14(P:VCC) IC112.14(P:VCC) IC113.14(P:VCC) IC114.14(P:VCC) IC115.14(P:VCC) IC116.14(P:VCC) IC117.14(P:VCC) IC118.14(P:VCC) IC119.14(P:VCC) IC120.14(P:VCC) IC121.14(P:VCC) IC122.14(P:VCC) IC123.14(P:VCC) IC124.24(VCC) IC125.14(P:VCC) IC126.4(P:VCC) IC127.4(P:VCC) IC128.4(P:VCC) IC129.14(VCC) IC130.14(VCC) IC131.14(VCC) IC132.14(P:VCC) IC133.14(VCC) IC134.14(VCC) IC135.14(VCC) IC136.14(P:VCC) IC137.14(P:VCC) IC138.14(P:VCC) IC139.14(P:VCC) IC140.14(P:VCC) IC141.14(P:VCC)

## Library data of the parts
IC1 IC124 = 74xx-jameco:74*154: 4-line to 16-line data SELECTOR/MULTIPLEXER
IC2 IC68 IC69 IC108-IC110 = 74xx-jameco:74*10: Triple 3-input NAND gate
IC3 IC4 IC14 IC15 IC53-IC55 IC91-IC93 IC99 IC111 IC112 IC122 IC123 IC125 IC132 = 74xx-jameco:74*04: Hex INVERTER
IC5-IC7 IC62-IC64 IC73-IC77 IC100-IC102 IC113-IC115 IC136-IC138 = 74xx-jameco:74*74: Dual D type positive edge triggered FLIP FLOP, preset and clear
IC8-IC10 IC18-IC20 IC65-IC67 IC70-IC72 IC119-IC121 IC139-IC141 = 74xx-jameco:74*20: Dual 4-input NAND gate
IC11-IC13 IC16 IC17 IC59-IC61 IC78-IC85 IC87 IC88 IC90 IC106 IC107 IC116-IC118 = 74xx-jameco:74*00: Quad 2-input NAND gate
IC21-IC23 IC30-IC32 IC38 IC39 IC45-IC47 = 74xx-jameco:74*02: Quad 2-input NOR gate
IC24-IC29 IC33-IC37 IC40-IC44 IC48-IC52 = 74xx-jameco:DS75452: Quad 2-input NAND gate, open collector output
IC56-IC58 IC94 IC95 IC126-IC128 = 74xx-jameco:74*73: Dual J-K FLIP FLOP, clear
IC86 IC89 IC133-IC135 = 74xx-jameco:74*30: 8-input NAND gate
IC96-IC98 IC103-IC105 IC129-IC131 = 74xx-us:74*51: AND-OR-INVERT gates/for S-type see 74S51
M916_1-M916_10 M916_12-M916_17 M916_19-M916_23 = dec-m:M916: Simple 36 pin connector/wire cable
SV1-SV10 = dec-con:DEC40PIN: PIN HEADER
